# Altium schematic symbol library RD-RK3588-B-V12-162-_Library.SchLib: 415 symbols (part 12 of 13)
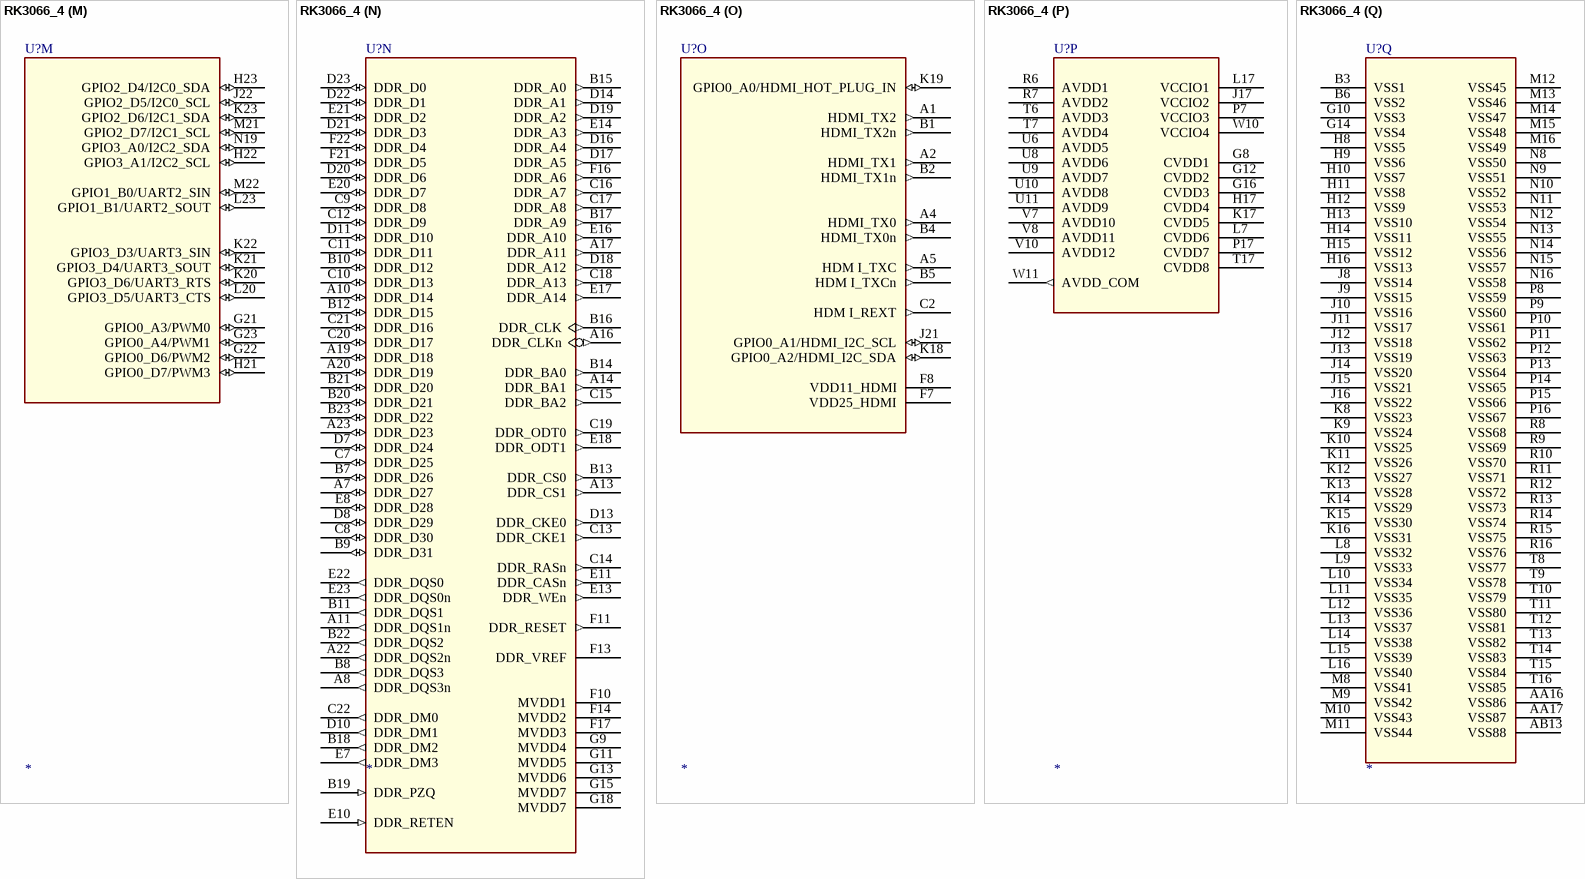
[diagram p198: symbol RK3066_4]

## RK3066_4
designator U?
footprint BGA453
part A pins: C3 LCD0_DEN (out), C4 LCD0_DCLK (out), C5 LCD0_VSYNC (out), C6 LCD0_HSYNC (out), D1 LCD0_D6 (out), D2 LCD0_D5 (out), D3 LCD0_D4 (out), D4 LCD0_D3 (out), D5 LCD0_D2 (out), D6 LCD0_D1 (out), E1 LCD0_D10 (out), E2 LCD0_D7 (out), E3 LCD0_D9 (out), E4 LCD0_D8 (out), E6 LCD0_D0 (out), F2 LCD0_D13 (out), F3 LCD0_D12 (out), F4 LCD0_D14 (out), F5 LCD0_D11 (out), G1 LCD0_D20 (out), G2 LCD0_D19 (out), G3 LCD0_D18 (out), G4 LCD0_D17 (out), G5 LCD0_D16 (out), G6 LCD0_D15 (out), H1 LCD0_D21 (out), H5 LCD0_D22 (out), H6 LCD0_D23 (out), H7 LCD0_VCC1 (power), J7 LCD0_VCC0 (power)
part B pins: H2 GPIO2_A0/LCD1_D0/SMC_A4 (io), H3 GPIO2_A1/LCD1_D1/SMC_A5 (io), H4 GPIO2_A2/LCD1_D2/SMC_A6 (io), J2 GPIO2_B7/LCD1_D14/SMC_A19/TS_D7 (io), J3 GPIO2_B6/LCD1_D14/SMC_A18/TS_SYNC (io), K1 GPIO2_C2/LCD1_D18/SMC_BIS_N1/TS_D5 (io), K2 GPIO2_C1/LCD1_D17/SMC_BIS_N0/TS_D6 (io), K3 GPIO2_B5/LCD1_D13/SMC_A17/TS_VALID (io), K4 GPIO2_C0/LCD1_D16/GPS_CLK/TS_CLKO (io), K7 LCD1_VCC (power), L1 GPIO2_C5/LCD1_D21/SPI1_RXD/TS_D2 (io), L2 GPIO2_C4/LCD1_D20/SPI1_CSN0/TS_D1 (io), L3 GPIO2_C3/LCD1_D19/SPI1_CLK/TS_D0 (io), L4 GPIO2_C7/LCD1_D23/SPI1_CSN1/TS_D4 (io), M2 GPIO2_C6/LCD1_D22/SPI1_RXD/TS_D3 (io)
part C pins: K5 CIF0_D5 (in), K6 CIF0_D2 (in), L5 CIF0_D9 (in), L6 CIF0_CLKIN (in), M3 CIF0_D8 (in), M7 CIF0_VCC (power), N1 CIF0_D4 (in), N2 CIF0_D3 (in), N3 CIF0_D7 (in), N4 GPIO1_B4/CIF0_D0 (io), N5 GPIO1_B3/CIF0_CLKO (io), N6 GPIO1_B5/CIF0_D1 (io), P1 CIF0_D6 (in), P2 CIF0_VSYNC (in), P3 CIF0_HREF (in), P4 GPIO1_B6/CIF0_D10 (io), P5 GPIO3_A3/I2C3_SCL (io), R2 GPIO3_A2/I2C3_SDA (io), R3 GPIO1_B7/CIF0_D11 (io)
part D pins: N7 CIF1_VCC (power), T1 GPIO1_C5/CIF1_D7/RMII_CRS_DVALID (io), T2 GPIO1_C0/CIF1_D2/RMII_CLKO (io), T3 GPIO1_C2/CIF1_D4/RMII_TXD1 (io), T4 GPIO1_C1/CIF1_D3/RMII_TX_EN (io), T5 GPIO1_C7/CIF1_D9/RMII_RXD0 (io), U1 GPIO1_D2/CIF1_CLKIN (io), U2 GPIO1_C4/CIF1_D6/RMII_RX_ERR (io), U3 GPIO1_C3/CIF1_D5/RMII_TXD0 (io), U4 GPIO1_D0/CIF1_VSYNC/MII_MD (io), U5 GPIO3_A5/I2C4_SCL (io), V2 GPIO1_D7/CIF1_CLKO (io), V3 GPIO1_C6/CIF1_D8/RMII_RXD1 (io), V4 GPIO1_D1/CIF1_HREF/MII_MDCLK (io), V5 GPIO3_A4/I2C4_SDA (io), W4 GPIO1_D6/CIF1_D11 (io)
part E pins: AA2 GPIO6_A4 (io), AA3 GPIO6_A5 (io), AA15 PVCC_3V3 (power), AB1 GPIO6_B0 (io), AB2 GPIO6_B1 (io), AB3 GPIO6_A1 (io), AB4 GPIO6_A7 (io), AB14 XOUT24M (out), AC1 GPIO6_A0 (io), AC2 GPIO6_A3 (io), AC4 GPIO6_A2 (io), AC5 GPIO6_A6 (io), AC13 DDRIO_RET_EN (out), AC14 XIN24M (in), U12 AVSS_APLL (power), U13 AVSS_DPLL (power), U14 AVSS_C/GPLL (power), V11 APLL_1V1 (power), V13 DPLL_1V1 (power), V14 C/GPLL_1V1 (power), V17 EFUSE (in), W13 PVDD_1V1 (power), Y1 CPU_PWROFF (out), Y2 CORE_PWROFF (out), Y3 DDRIO_PWROFF (out), Y4 GPIO6_B2 (io), Y5 GPIO6_B3 (io), Y13 CLKIN_32K (in), Y14 NPOR (in)
part F pins: AB15 HOST_RKELVIN (out), AB16 OTG_DM (io), AB17 HOST_DM (io), AC16 OTG_DP (io), AC17 HOST_DP (io), F19 GPIO0_A6/HOST_DRV (io), F20 TDO (out), G19 TDI/CPR_BYPASS (in), G20 TRSTN (in), H18 TCK/HSSCAN_SHIFT_CLOCK (in), H19 TMS/PLL_BYPASS (io), H20 RECOVER (in), P20 GPIO0_A5/OTG_DRV (io), U15 USBVDD_1V1 (power), U16 USBVDD_2V5 (power), V16 USBVDD_3V3 (power), W1 SARADC_ANI0 (in), W2 SARADC_ANI2 (in), W3 SARADC_ANI1 (in), W16 OTG_RKELVIN (out), W17 OTG_VBUS (in), Y17 OTG_ID (in)
part G pins: AA4 GPIO1_A4/UART1_RX/SPI0_CSN0 (io), AA5 GPIO4_B7/SPI0_CSN1 (io), AB5 GPIO1_A5/UART1_TX/SPI0_CLK (io), AB6 GPIO1_A6/UART1_CTSN/SPI0_RXD (io), AC7 GPIO1_A7/UART1_RTSN/SPI0_TXD (io), W18 AP1_VCC (power)
part H pins: AC23 GPIO3_B6/SDMMC0_DET (io), N22 GPIO3_B4/SDMMC0_D2 (io), N23 GPIO3_B5/SDMMC0_D3 (io), P18 GPIO3_A6/SDMMC0_RSTNO (io), P22 GPIO3_B3/SDMMC0_D1 (io), P23 GPIO3_B7/SDMMC0_WRITE_PRT (io), R22 GPIO3_A7/SDMMC0_PWR_EN (io), T21 GPIO3_B0/SDMMC0_CLKOUT (io), U19 GPIO3_B2/SDMMC0_D0 (io), U20 GPIO3_B1/SDMMC0_CMD (io)
part I pins: AA6 GPIO3_C1/SDMMC1_D0 (io), AA7 GPIO3_C2/SDMMC1_D1 (io), AA8 GPIO3_C7/SDMMC1_WRITE_PRT (io), AA9 GPIO1_A1/UART0_SOUT (io), AA10 GPIO0_C3/I2S1_LRCK_TX (io), AA12 GPIO1_A0/UART0_SIN (io), AB7 GPIO3_C0/SDMMC1_CMD (io), AB8 GPIO3_D2/SDMMC1_INT (io), AB9 GPIO0_C1/I2S1_SCLK (io), AB10 GPIO3_D1/SDMMC1_BACKEND (io), AB11 GPIO1_A2/UART0_CTS (io), AC8 GPIO3_C4/SDMMC1_D3 (io), AC10 GPIO3_C3/SDMMC1_D2 (io), AC11 GPIO0_C2/I2S1_LRCK_RX (io), U18 AP0_VCC (io), W6 GPIO3_C6/SDMMC1_DET (io), W7 GPIO0_C4/I2S1_SDI (io), W8 GPIO1_A3/UART0_RTS (io), Y6 GPIO3_C5/SDMMC1_CLKO (io), Y7 GPIO3_D0/SDMMC1_PWR_EN (io), Y8 GPIO0_C5/I2S1_SDO (io), Y11 GPIO0_C0/I2S1_CLK (io)
part J pins: AA11 GPIO4_C0/SMC_D0/TRACE_D0 (io), AA13 GPIO4_C4/SMC_D4/TRACE_D4 (io), AA14 GPIO4_D0/SMC_D8/TRACE_D8 (io), AA18 GPIO4_D3/SMC_D11/TRACE_D11 (io), AA19 GPIO4_D1/SMC_D9/TRACE_D9 (io), AA20 GPIO4_D5/SMC_D13/TRACE_D13 (io), AA21 GPIO0_D5/I2S2_SDO/SMC_A1 (io), AA22 GPIO0_D4/I2S2_SDI/SMC_A0 (io), AB12 GPIO4_C6/SMC_D6/TRACE_D6 (io), AB18 GPIO4_C3/SMC_D3/TRACE_D3 (io), AB19 GPIO4_D6/SMC_D14/TRACE_D14 (io), AB20 GPIO0_C7/SMC_A3/TRACE_CTL (io), AB21 GPIO0_D2/I2S2_LRCK_RX/SMC_OEN (io), AB23 GPIO0_C6/SMC_A2/TRACE_CLK (io), AC19 GPIO4_D7/SMC_D15/TRACE_D15 (io), AC20 GPIO4_D4/SMC_D12/TRACE_D12 (io), AC22 GPIO0_D3/I2S2_LRCK_TX/SMC_ADVN (io), R17 SMC_VCC (power), W14 GPIO4_C7/SMC_D7/TRACE_D7 (io), Y10 GPIO4_C1/SMC_D1/TRACE_D1 (io), Y16 GPIO4_C2/SMC_D2/TRACE_D2 (io), Y18 GPIO4_C5/SMC_D5/TRACE_D5 (io), Y19 GPIO4_D2/SMC_D10/TRACE_D10 (io), Y20 GPIO0_D1/I2S2_SCLK/SMC_WEN (io), Y23 GPIO0_D0/I2S2_CLK/SMC_CSN0 (io)
part K pins: AB22 FLASH_D0/EMMC_D0 (io), M17 FLASH_VCC0 (power), N17 FLASH_VCC1 (power), T18 GPIO4_B0/FLASH_CS1 (io), T19 GPIO4_B1/FLASH_CS2/EMMC_CMD (io), T20 GPIO4_B2/FLASH_CS3/EMMC_RST (io), T22 FLASH_ALE (out), T23 FLASH_CS0 (out), U21 FLASH_WP/EMMC_PWR_EN (out), U22 FLASH_D7/EMMC_D7 (io), U23 FLASH_D6/EMMC_D6 (io), V19 FLASH_RDN (out), V20 FLASH_CLE (out), V21 FLASH_RDY (out), V22 FLASH_D5/EMMC_D5 (io), W20 FLASH_WRN (out), W21 GPIO3_D7/FLASH_DQS/EMMC_CLKO (io), W22 FLASH_D4/EMMC_D4 (io), W23 FLASH_D3/EMMC_D3 (io), Y21 FLASH_D1/EMMC_D1 (io), Y22 FLASH_D2/EMMC_D2 (io)
part L pins: L18 GPIO0_B4/I2S0_D0 (io), L19 GPIO0_B7/I2S0_D3 (io), L21 GPIO1_B2/SPDIF_TX (io), L22 GPIO0_B5/I2S0_D1 (io), N18 GPIO0_B6/I2S0_D2 (io), N20 GPIO0_B2/I2S0_LRCK_RX (io), N21 GPIO0_B1/I2S0_SCLK (io), P19 GPIO0_A7/I2S0_SDI (io), P21 GPIO0_B3/I2S0_LRCK_TX (io), R21 GPIO0_B0/I2S0_CLK (io)
part M pins: G21 GPIO0_A3/PWM0 (io), G22 GPIO0_D6/PWM2 (io), G23 GPIO0_A4/PWM1 (io), H21 GPIO0_D7/PWM3 (io), H22 GPIO3_A1/I2C2_SCL (io), H23 GPIO2_D4/I2C0_SDA (io), J22 GPIO2_D5/I2C0_SCL (io), K20 GPIO3_D6/UART3_RTS (io), K21 GPIO3_D4/UART3_SOUT (io), K22 GPIO3_D3/UART3_SIN (io), K23 GPIO2_D6/I2C1_SDA (io), L20 GPIO3_D5/UART3_CTS (io), L23 GPIO1_B1/UART2_SOUT (io), M21 GPIO2_D7/I2C1_SCL (io), M22 GPIO1_B0/UART2_SIN (io), N19 GPIO3_A0/I2C2_SDA (io)
part N pins: A7 DDR_D27 (io), A8 DDR_DQS3n (out), A10 DDR_D14 (io), A11 DDR_DQS1n (out), A13 DDR_CS1 (out), A14 DDR_BA1 (out), A16 DDR_CLKn (out), A17 DDR_A11 (out), A19 DDR_D18 (io), A20 DDR_D19 (io), A22 DDR_DQS2n (out), A23 DDR_D23 (io), B7 DDR_D26 (io), B8 DDR_DQS3 (out), B9 DDR_D31 (io), B10 DDR_D12 (io), B11 DDR_DQS1 (out), B12 DDR_D15 (io), B13 DDR_CS0 (out), B14 DDR_BA0 (out), B15 DDR_A0 (out), B16 DDR_CLK (out), B17 DDR_A9 (out), B18 DDR_DM2 (out), B19 DDR_PZQ (in), B20 DDR_D21 (io), B21 DDR_D20 (io), B22 DDR_DQS2 (out), B23 DDR_D22 (io), C7 DDR_D25 (io), C8 DDR_D30 (io), C9 DDR_D8 (io), C10 DDR_D13 (io), C11 DDR_D11 (io), C12 DDR_D9 (io), C13 DDR_CKE1 (out), C14 DDR_RASn (out), C15 DDR_BA2 (out), C16 DDR_A7 (out), C17 DDR_A8 (out), C18 DDR_A13 (out), C19 DDR_ODT0 (out), C20 DDR_D17 (io), C21 DDR_D16 (io), C22 DDR_DM0 (out), D7 DDR_D24 (io), D8 DDR_D29 (io), D10 DDR_DM1 (out), D11 DDR_D10 (io), D13 DDR_CKE0 (out), D14 DDR_A1 (out), D16 DDR_A4 (out), D17 DDR_A5 (out), D18 DDR_A12 (out), D19 DDR_A2 (out), D20 DDR_D6 (io), D21 DDR_D3 (io), D22 DDR_D1 (io), D23 DDR_D0 (io), E7 DDR_DM3 (out), E8 DDR_D28 (io), E10 DDR_RETEN (in), E11 DDR_CASn (out), E13 DDR_WEn (out), E14 DDR_A3 (out), E16 DDR_A10 (out), E17 DDR_A14 (out), E18 DDR_ODT1 (out), E20 DDR_D7 (io), E21 DDR_D2 (io), E22 DDR_DQS0 (out), E23 DDR_DQS0n (out), F10 MVDD1 (power), F11 DDR_RESET (out), F13 DDR_VREF (power), F14 MVDD2 (power), F16 DDR_A6 (out), F17 MVDD3 (power), F21 DDR_D5 (io), F22 DDR_D4 (io), G9 MVDD4 (power), G11 MVDD5 (power), G13 MVDD6 (power), G15 MVDD7 (power), G18 MVDD7 (power)
part O pins: A1 HDMI_TX2 (out), A2 HDMI_TX1 (out), A4 HDMI_TX0 (out), A5 HDM I_TXC (out), B1 HDMI_TX2n (out), B2 HDMI_TX1n (out), B4 HDMI_TX0n (out), B5 HDM I_TXCn (out), C2 HDM I_REXT (out), F7 VDD25_HDMI (power), F8 VDD11_HDMI (power), J21 GPIO0_A1/HDMI_I2C_SCL (io), K18 GPIO0_A2/HDMI_I2C_SDA (io), K19 GPIO0_A0/HDMI_HOT_PLUG_IN (io)
part P pins: G8 CVDD1 (power), G12 CVDD2 (power), G16 CVDD3 (power), H17 CVDD4 (power), J17 VCCIO2 (power), K17 CVDD5 (power), L7 CVDD6 (power), L17 VCCIO1 (power), P7 VCCIO3 (power), P17 CVDD7 (power), R6 AVDD1 (power), R7 AVDD2 (power), T6 AVDD3 (power), T7 AVDD4 (power), T17 CVDD8 (power), U6 AVDD5 (power), U8 AVDD6 (power), U9 AVDD7 (power), U10 AVDD8 (power), U11 AVDD9 (power), V7 AVDD10 (power), V8 AVDD11 (power), V10 AVDD12 (power), W10 VCCIO4 (power), W11 AVDD_COM (out)
part Q pins: AA16 VSS86 (power), AA17 VSS87 (power), AB13 VSS88 (power), B3 VSS1 (power), B6 VSS2 (power), G10 VSS3 (power), G14 VSS4 (power), H8 VSS5 (power), H9 VSS6 (power), H10 VSS7 (power), H11 VSS8 (power), H12 VSS9 (power), H13 VSS10 (power), H14 VSS11 (power), H15 VSS12 (power), H16 VSS13 (power), J8 VSS14 (power), J9 VSS15 (power), J10 VSS16 (power), J11 VSS17 (power), J12 VSS18 (power), J13 VSS19 (power), J14 VSS20 (power), J15 VSS21 (power), J16 VSS22 (power), K8 VSS23 (power), K9 VSS24 (power), K10 VSS25 (power), K11 VSS26 (power), K12 VSS27 (power), K13 VSS28 (power), K14 VSS29 (power), K15 VSS30 (power), K16 VSS31 (power), L8 VSS32 (power), L9 VSS33 (power), L10 VSS34 (power), L11 VSS35 (power), L12 VSS36 (power), L13 VSS37 (power), L14 VSS38 (power), L15 VSS39 (power), L16 VSS40 (power), M8 VSS41 (power), M9 VSS42 (power), M10 VSS43 (power), M11 VSS44 (power), M12 VSS45 (power), M13 VSS46 (power), M14 VSS47 (power), M15 VSS48 (power), M16 VSS49 (power), N8 VSS50 (power), N9 VSS51 (power), N10 VSS52 (power), N11 VSS53 (power), N12 VSS54 (power), N13 VSS55 (power), N14 VSS56 (power), N15 VSS57 (power), N16 VSS58 (power), P8 VSS59 (power), P9 VSS60 (power), P10 VSS61 (power), P11 VSS62 (power), P12 VSS63 (power), P13 VSS64 (power), P14 VSS65 (power), P15 VSS66 (power), P16 VSS67 (power), R8 VSS68 (power), R9 VSS69 (power), R10 VSS70 (power), R11 VSS71 (power), R12 VSS72 (power), R13 VSS73 (power), R14 VSS74 (power), R15 VSS75 (power), R16 VSS76 (power), T8 VSS77 (power), T9 VSS78 (power), T10 VSS79 (power), T11 VSS80 (power), T12 VSS81 (power), T13 VSS82 (power), T14 VSS83 (power), T15 VSS84 (power), T16 VSS85 (power)

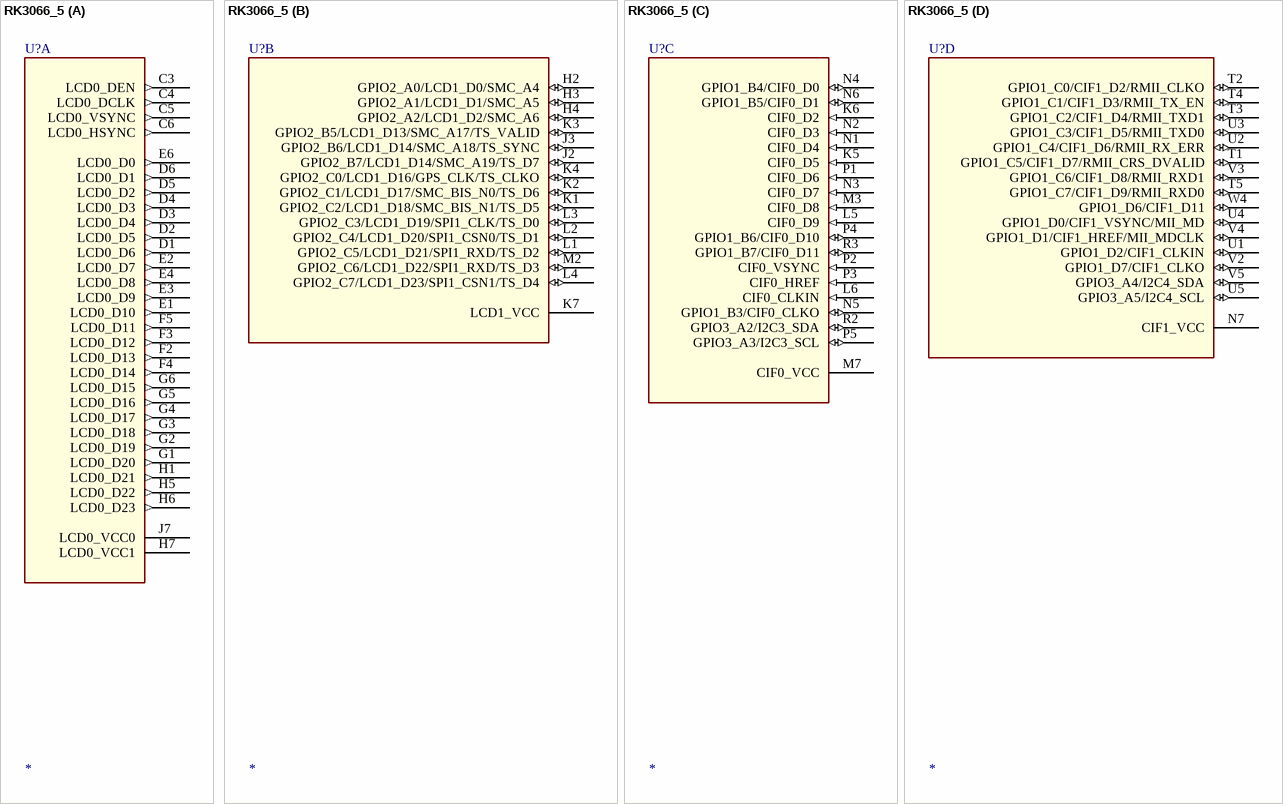
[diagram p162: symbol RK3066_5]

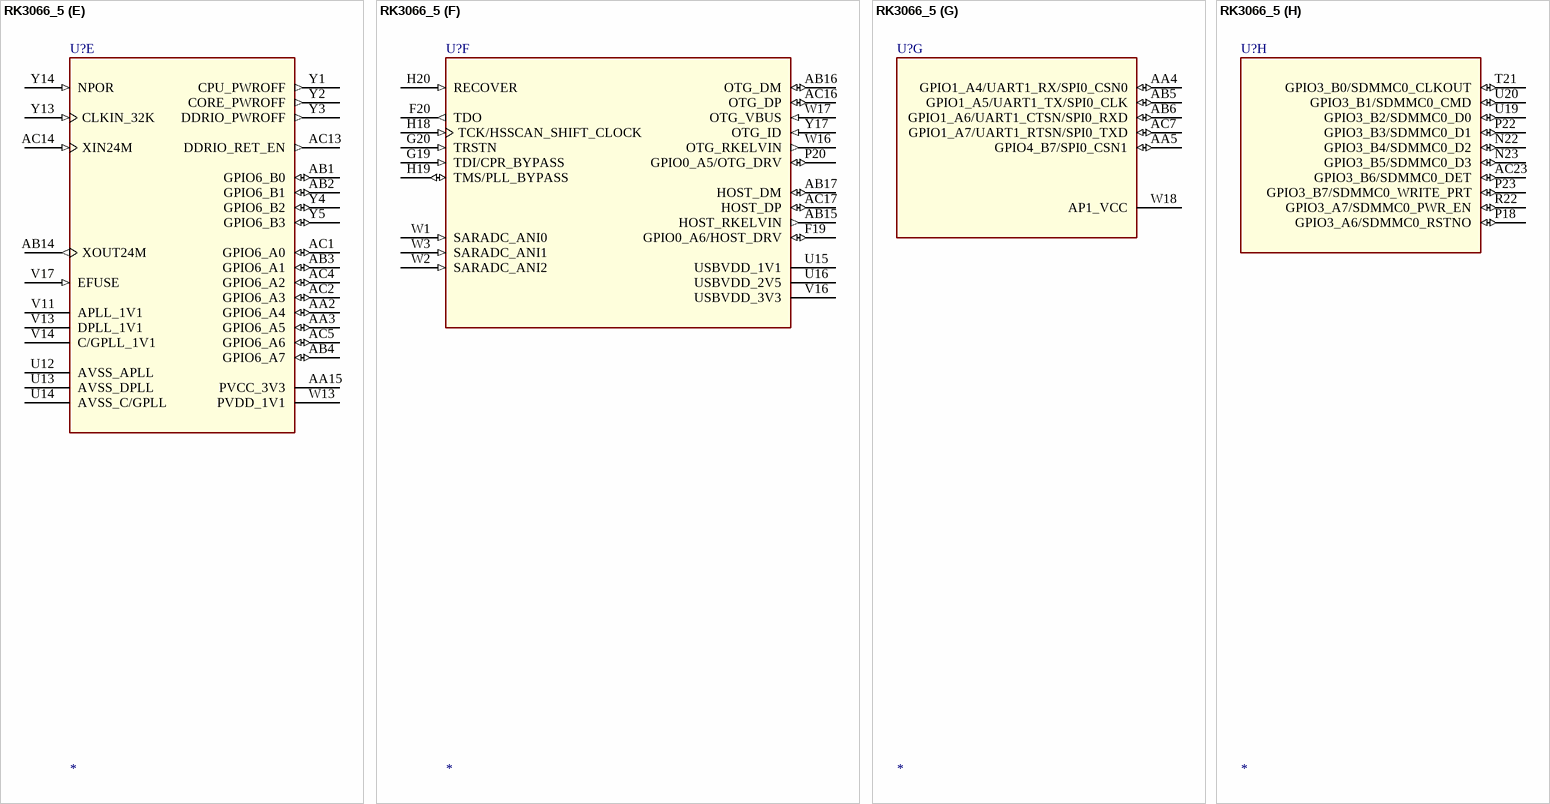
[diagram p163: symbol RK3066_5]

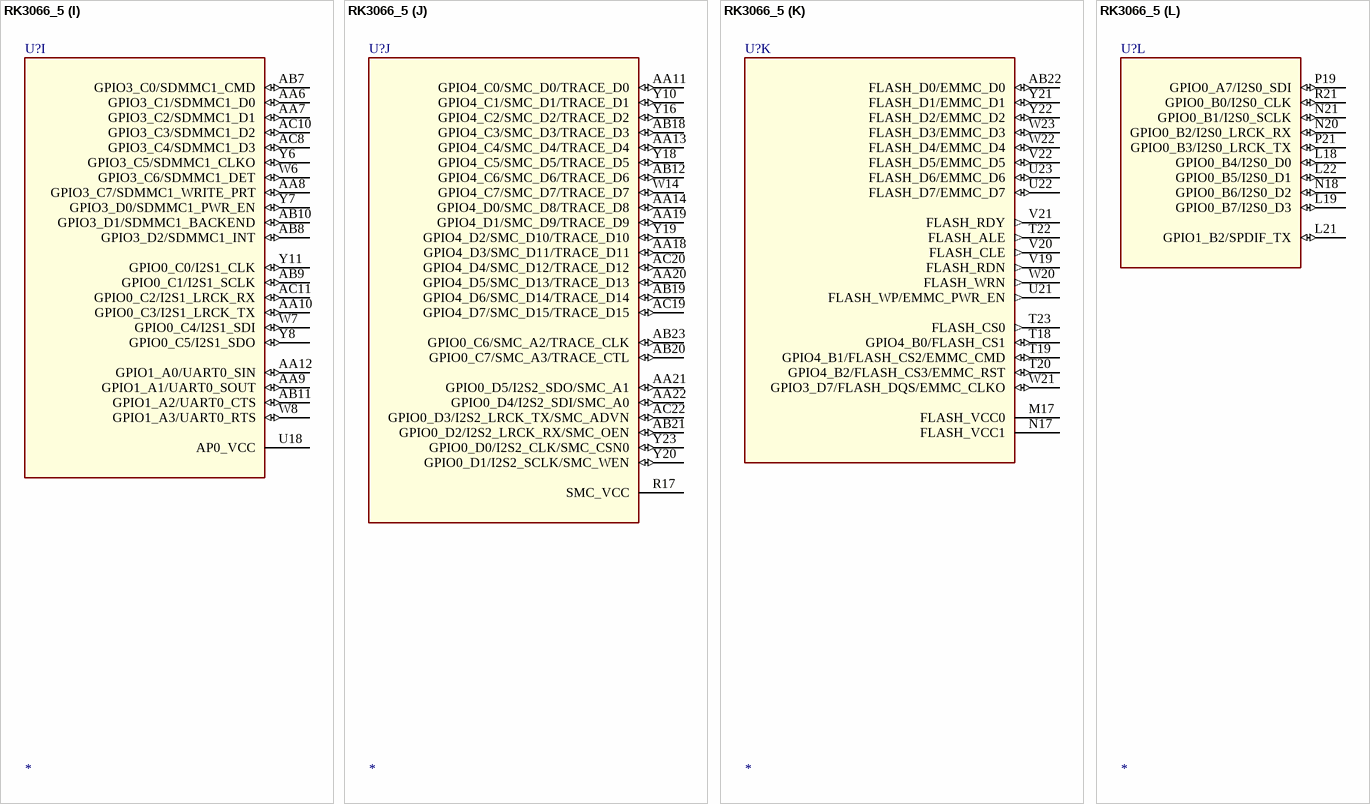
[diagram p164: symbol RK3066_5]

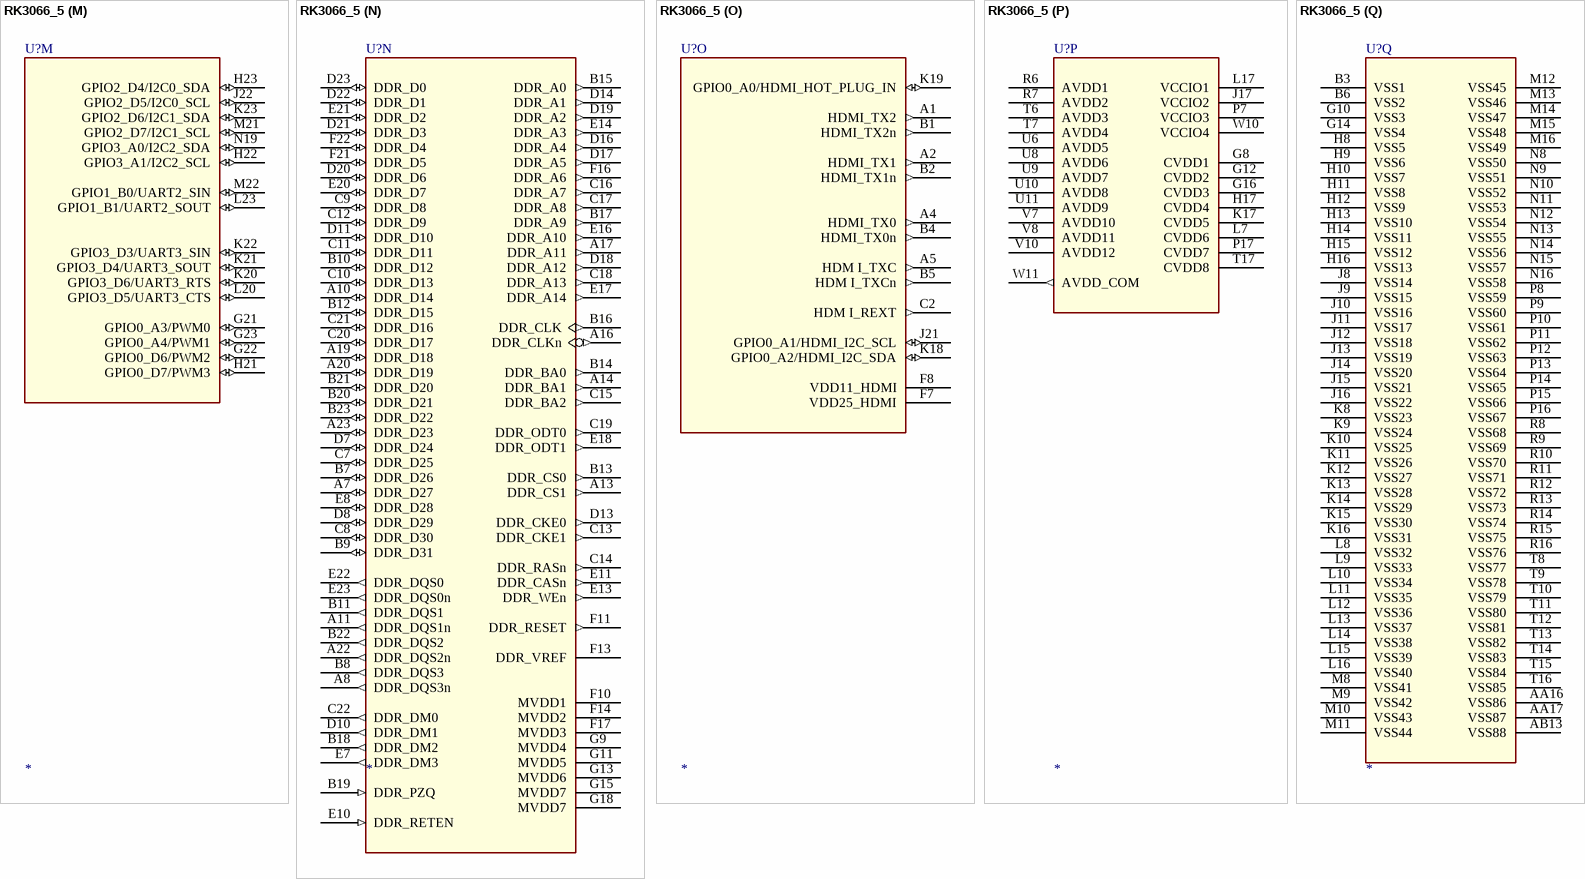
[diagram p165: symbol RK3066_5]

## RK3066_5
designator U?
footprint BGA453
part A pins: C3 LCD0_DEN (out), C4 LCD0_DCLK (out), C5 LCD0_VSYNC (out), C6 LCD0_HSYNC (out), D1 LCD0_D6 (out), D2 LCD0_D5 (out), D3 LCD0_D4 (out), D4 LCD0_D3 (out), D5 LCD0_D2 (out), D6 LCD0_D1 (out), E1 LCD0_D10 (out), E2 LCD0_D7 (out), E3 LCD0_D9 (out), E4 LCD0_D8 (out), E6 LCD0_D0 (out), F2 LCD0_D13 (out), F3 LCD0_D12 (out), F4 LCD0_D14 (out), F5 LCD0_D11 (out), G1 LCD0_D20 (out), G2 LCD0_D19 (out), G3 LCD0_D18 (out), G4 LCD0_D17 (out), G5 LCD0_D16 (out), G6 LCD0_D15 (out), H1 LCD0_D21 (out), H5 LCD0_D22 (out), H6 LCD0_D23 (out), H7 LCD0_VCC1 (power), J7 LCD0_VCC0 (power)
part B pins: H2 GPIO2_A0/LCD1_D0/SMC_A4 (io), H3 GPIO2_A1/LCD1_D1/SMC_A5 (io), H4 GPIO2_A2/LCD1_D2/SMC_A6 (io), J2 GPIO2_B7/LCD1_D14/SMC_A19/TS_D7 (io), J3 GPIO2_B6/LCD1_D14/SMC_A18/TS_SYNC (io), K1 GPIO2_C2/LCD1_D18/SMC_BIS_N1/TS_D5 (io), K2 GPIO2_C1/LCD1_D17/SMC_BIS_N0/TS_D6 (io), K3 GPIO2_B5/LCD1_D13/SMC_A17/TS_VALID (io), K4 GPIO2_C0/LCD1_D16/GPS_CLK/TS_CLKO (io), K7 LCD1_VCC (power), L1 GPIO2_C5/LCD1_D21/SPI1_RXD/TS_D2 (io), L2 GPIO2_C4/LCD1_D20/SPI1_CSN0/TS_D1 (io), L3 GPIO2_C3/LCD1_D19/SPI1_CLK/TS_D0 (io), L4 GPIO2_C7/LCD1_D23/SPI1_CSN1/TS_D4 (io), M2 GPIO2_C6/LCD1_D22/SPI1_RXD/TS_D3 (io)
part C pins: K5 CIF0_D5 (in), K6 CIF0_D2 (in), L5 CIF0_D9 (in), L6 CIF0_CLKIN (in), M3 CIF0_D8 (in), M7 CIF0_VCC (power), N1 CIF0_D4 (in), N2 CIF0_D3 (in), N3 CIF0_D7 (in), N4 GPIO1_B4/CIF0_D0 (io), N5 GPIO1_B3/CIF0_CLKO (io), N6 GPIO1_B5/CIF0_D1 (io), P1 CIF0_D6 (in), P2 CIF0_VSYNC (in), P3 CIF0_HREF (in), P4 GPIO1_B6/CIF0_D10 (io), P5 GPIO3_A3/I2C3_SCL (io), R2 GPIO3_A2/I2C3_SDA (io), R3 GPIO1_B7/CIF0_D11 (io)
part D pins: N7 CIF1_VCC (power), T1 GPIO1_C5/CIF1_D7/RMII_CRS_DVALID (io), T2 GPIO1_C0/CIF1_D2/RMII_CLKO (io), T3 GPIO1_C2/CIF1_D4/RMII_TXD1 (io), T4 GPIO1_C1/CIF1_D3/RMII_TX_EN (io), T5 GPIO1_C7/CIF1_D9/RMII_RXD0 (io), U1 GPIO1_D2/CIF1_CLKIN (io), U2 GPIO1_C4/CIF1_D6/RMII_RX_ERR (io), U3 GPIO1_C3/CIF1_D5/RMII_TXD0 (io), U4 GPIO1_D0/CIF1_VSYNC/MII_MD (io), U5 GPIO3_A5/I2C4_SCL (io), V2 GPIO1_D7/CIF1_CLKO (io), V3 GPIO1_C6/CIF1_D8/RMII_RXD1 (io), V4 GPIO1_D1/CIF1_HREF/MII_MDCLK (io), V5 GPIO3_A4/I2C4_SDA (io), W4 GPIO1_D6/CIF1_D11 (io)
part E pins: AA2 GPIO6_A4 (io), AA3 GPIO6_A5 (io), AA15 PVCC_3V3 (power), AB1 GPIO6_B0 (io), AB2 GPIO6_B1 (io), AB3 GPIO6_A1 (io), AB4 GPIO6_A7 (io), AB14 XOUT24M (out), AC1 GPIO6_A0 (io), AC2 GPIO6_A3 (io), AC4 GPIO6_A2 (io), AC5 GPIO6_A6 (io), AC13 DDRIO_RET_EN (out), AC14 XIN24M (in), U12 AVSS_APLL (power), U13 AVSS_DPLL (power), U14 AVSS_C/GPLL (power), V11 APLL_1V1 (power), V13 DPLL_1V1 (power), V14 C/GPLL_1V1 (power), V17 EFUSE (in), W13 PVDD_1V1 (power), Y1 CPU_PWROFF (out), Y2 CORE_PWROFF (out), Y3 DDRIO_PWROFF (out), Y4 GPIO6_B2 (io), Y5 GPIO6_B3 (io), Y13 CLKIN_32K (in), Y14 NPOR (in)
part F pins: AB15 HOST_RKELVIN (out), AB16 OTG_DM (io), AB17 HOST_DM (io), AC16 OTG_DP (io), AC17 HOST_DP (io), F19 GPIO0_A6/HOST_DRV (io), F20 TDO (out), G19 TDI/CPR_BYPASS (in), G20 TRSTN (in), H18 TCK/HSSCAN_SHIFT_CLOCK (in), H19 TMS/PLL_BYPASS (io), H20 RECOVER (in), P20 GPIO0_A5/OTG_DRV (io), U15 USBVDD_1V1 (power), U16 USBVDD_2V5 (power), V16 USBVDD_3V3 (power), W1 SARADC_ANI0 (in), W2 SARADC_ANI2 (in), W3 SARADC_ANI1 (in), W16 OTG_RKELVIN (out), W17 OTG_VBUS (in), Y17 OTG_ID (in)
part G pins: AA4 GPIO1_A4/UART1_RX/SPI0_CSN0 (io), AA5 GPIO4_B7/SPI0_CSN1 (io), AB5 GPIO1_A5/UART1_TX/SPI0_CLK (io), AB6 GPIO1_A6/UART1_CTSN/SPI0_RXD (io), AC7 GPIO1_A7/UART1_RTSN/SPI0_TXD (io), W18 AP1_VCC (power)
part H pins: AC23 GPIO3_B6/SDMMC0_DET (io), N22 GPIO3_B4/SDMMC0_D2 (io), N23 GPIO3_B5/SDMMC0_D3 (io), P18 GPIO3_A6/SDMMC0_RSTNO (io), P22 GPIO3_B3/SDMMC0_D1 (io), P23 GPIO3_B7/SDMMC0_WRITE_PRT (io), R22 GPIO3_A7/SDMMC0_PWR_EN (io), T21 GPIO3_B0/SDMMC0_CLKOUT (io), U19 GPIO3_B2/SDMMC0_D0 (io), U20 GPIO3_B1/SDMMC0_CMD (io)
part I pins: AA6 GPIO3_C1/SDMMC1_D0 (io), AA7 GPIO3_C2/SDMMC1_D1 (io), AA8 GPIO3_C7/SDMMC1_WRITE_PRT (io), AA9 GPIO1_A1/UART0_SOUT (io), AA10 GPIO0_C3/I2S1_LRCK_TX (io), AA12 GPIO1_A0/UART0_SIN (io), AB7 GPIO3_C0/SDMMC1_CMD (io), AB8 GPIO3_D2/SDMMC1_INT (io), AB9 GPIO0_C1/I2S1_SCLK (io), AB10 GPIO3_D1/SDMMC1_BACKEND (io), AB11 GPIO1_A2/UART0_CTS (io), AC8 GPIO3_C4/SDMMC1_D3 (io), AC10 GPIO3_C3/SDMMC1_D2 (io), AC11 GPIO0_C2/I2S1_LRCK_RX (io), U18 AP0_VCC (power), W6 GPIO3_C6/SDMMC1_DET (io), W7 GPIO0_C4/I2S1_SDI (io), W8 GPIO1_A3/UART0_RTS (io), Y6 GPIO3_C5/SDMMC1_CLKO (io), Y7 GPIO3_D0/SDMMC1_PWR_EN (io), Y8 GPIO0_C5/I2S1_SDO (io), Y11 GPIO0_C0/I2S1_CLK (io)
part J pins: AA11 GPIO4_C0/SMC_D0/TRACE_D0 (io), AA13 GPIO4_C4/SMC_D4/TRACE_D4 (io), AA14 GPIO4_D0/SMC_D8/TRACE_D8 (io), AA18 GPIO4_D3/SMC_D11/TRACE_D11 (io), AA19 GPIO4_D1/SMC_D9/TRACE_D9 (io), AA20 GPIO4_D5/SMC_D13/TRACE_D13 (io), AA21 GPIO0_D5/I2S2_SDO/SMC_A1 (io), AA22 GPIO0_D4/I2S2_SDI/SMC_A0 (io), AB12 GPIO4_C6/SMC_D6/TRACE_D6 (io), AB18 GPIO4_C3/SMC_D3/TRACE_D3 (io), AB19 GPIO4_D6/SMC_D14/TRACE_D14 (io), AB20 GPIO0_C7/SMC_A3/TRACE_CTL (io), AB21 GPIO0_D2/I2S2_LRCK_RX/SMC_OEN (io), AB23 GPIO0_C6/SMC_A2/TRACE_CLK (io), AC19 GPIO4_D7/SMC_D15/TRACE_D15 (io), AC20 GPIO4_D4/SMC_D12/TRACE_D12 (io), AC22 GPIO0_D3/I2S2_LRCK_TX/SMC_ADVN (io), R17 SMC_VCC (power), W14 GPIO4_C7/SMC_D7/TRACE_D7 (io), Y10 GPIO4_C1/SMC_D1/TRACE_D1 (io), Y16 GPIO4_C2/SMC_D2/TRACE_D2 (io), Y18 GPIO4_C5/SMC_D5/TRACE_D5 (io), Y19 GPIO4_D2/SMC_D10/TRACE_D10 (io), Y20 GPIO0_D1/I2S2_SCLK/SMC_WEN (io), Y23 GPIO0_D0/I2S2_CLK/SMC_CSN0 (io)
part K pins: AB22 FLASH_D0/EMMC_D0 (io), M17 FLASH_VCC0 (power), N17 FLASH_VCC1 (power), T18 GPIO4_B0/FLASH_CS1 (io), T19 GPIO4_B1/FLASH_CS2/EMMC_CMD (io), T20 GPIO4_B2/FLASH_CS3/EMMC_RST (io), T22 FLASH_ALE (out), T23 FLASH_CS0 (out), U21 FLASH_WP/EMMC_PWR_EN (out), U22 FLASH_D7/EMMC_D7 (io), U23 FLASH_D6/EMMC_D6 (io), V19 FLASH_RDN (out), V20 FLASH_CLE (out), V21 FLASH_RDY (out), V22 FLASH_D5/EMMC_D5 (io), W20 FLASH_WRN (out), W21 GPIO3_D7/FLASH_DQS/EMMC_CLKO (io), W22 FLASH_D4/EMMC_D4 (io), W23 FLASH_D3/EMMC_D3 (io), Y21 FLASH_D1/EMMC_D1 (io), Y22 FLASH_D2/EMMC_D2 (io)
part L pins: L18 GPIO0_B4/I2S0_D0 (io), L19 GPIO0_B7/I2S0_D3 (io), L21 GPIO1_B2/SPDIF_TX (io), L22 GPIO0_B5/I2S0_D1 (io), N18 GPIO0_B6/I2S0_D2 (io), N20 GPIO0_B2/I2S0_LRCK_RX (io), N21 GPIO0_B1/I2S0_SCLK (io), P19 GPIO0_A7/I2S0_SDI (io), P21 GPIO0_B3/I2S0_LRCK_TX (io), R21 GPIO0_B0/I2S0_CLK (io)
part M pins: G21 GPIO0_A3/PWM0 (io), G22 GPIO0_D6/PWM2 (io), G23 GPIO0_A4/PWM1 (io), H21 GPIO0_D7/PWM3 (io), H22 GPIO3_A1/I2C2_SCL (io), H23 GPIO2_D4/I2C0_SDA (io), J22 GPIO2_D5/I2C0_SCL (io), K20 GPIO3_D6/UART3_RTS (io), K21 GPIO3_D4/UART3_SOUT (io), K22 GPIO3_D3/UART3_SIN (io), K23 GPIO2_D6/I2C1_SDA (io), L20 GPIO3_D5/UART3_CTS (io), L23 GPIO1_B1/UART2_SOUT (io), M21 GPIO2_D7/I2C1_SCL (io), M22 GPIO1_B0/UART2_SIN (io), N19 GPIO3_A0/I2C2_SDA (io)
part N pins: A7 DDR_D27 (io), A8 DDR_DQS3n (out), A10 DDR_D14 (io), A11 DDR_DQS1n (out), A13 DDR_CS1 (out), A14 DDR_BA1 (out), A16 DDR_CLKn (out), A17 DDR_A11 (out), A19 DDR_D18 (io), A20 DDR_D19 (io), A22 DDR_DQS2n (out), A23 DDR_D23 (io), B7 DDR_D26 (io), B8 DDR_DQS3 (out), B9 DDR_D31 (io), B10 DDR_D12 (io), B11 DDR_DQS1 (out), B12 DDR_D15 (io), B13 DDR_CS0 (out), B14 DDR_BA0 (out), B15 DDR_A0 (out), B16 DDR_CLK (out), B17 DDR_A9 (out), B18 DDR_DM2 (out), B19 DDR_PZQ (in), B20 DDR_D21 (io), B21 DDR_D20 (io), B22 DDR_DQS2 (out), B23 DDR_D22 (io), C7 DDR_D25 (io), C8 DDR_D30 (io), C9 DDR_D8 (io), C10 DDR_D13 (io), C11 DDR_D11 (io), C12 DDR_D9 (io), C13 DDR_CKE1 (out), C14 DDR_RASn (out), C15 DDR_BA2 (out), C16 DDR_A7 (out), C17 DDR_A8 (out), C18 DDR_A13 (out), C19 DDR_ODT0 (out), C20 DDR_D17 (io), C21 DDR_D16 (io), C22 DDR_DM0 (out), D7 DDR_D24 (io), D8 DDR_D29 (io), D10 DDR_DM1 (out), D11 DDR_D10 (io), D13 DDR_CKE0 (out), D14 DDR_A1 (out), D16 DDR_A4 (out), D17 DDR_A5 (out), D18 DDR_A12 (out), D19 DDR_A2 (out), D20 DDR_D6 (io), D21 DDR_D3 (io), D22 DDR_D1 (io), D23 DDR_D0 (io), E7 DDR_DM3 (out), E8 DDR_D28 (io), E10 DDR_RETEN (in), E11 DDR_CASn (out), E13 DDR_WEn (out), E14 DDR_A3 (out), E16 DDR_A10 (out), E17 DDR_A14 (out), E18 DDR_ODT1 (out), E20 DDR_D7 (io), E21 DDR_D2 (io), E22 DDR_DQS0 (out), E23 DDR_DQS0n (out), F10 MVDD1 (power), F11 DDR_RESET (out), F13 DDR_VREF (power), F14 MVDD2 (power), F16 DDR_A6 (out), F17 MVDD3 (power), F21 DDR_D5 (io), F22 DDR_D4 (io), G9 MVDD4 (power), G11 MVDD5 (power), G13 MVDD6 (power), G15 MVDD7 (power), G18 MVDD7 (power)
part O pins: A1 HDMI_TX2 (out), A2 HDMI_TX1 (out), A4 HDMI_TX0 (out), A5 HDM I_TXC (out), B1 HDMI_TX2n (out), B2 HDMI_TX1n (out), B4 HDMI_TX0n (out), B5 HDM I_TXCn (out), C2 HDM I_REXT (out), F7 VDD25_HDMI (power), F8 VDD11_HDMI (power), J21 GPIO0_A1/HDMI_I2C_SCL (io), K18 GPIO0_A2/HDMI_I2C_SDA (io), K19 GPIO0_A0/HDMI_HOT_PLUG_IN (io)
part P pins: G8 CVDD1 (power), G12 CVDD2 (power), G16 CVDD3 (power), H17 CVDD4 (power), J17 VCCIO2 (power), K17 CVDD5 (power), L7 CVDD6 (power), L17 VCCIO1 (power), P7 VCCIO3 (power), P17 CVDD7 (power), R6 AVDD1 (power), R7 AVDD2 (power), T6 AVDD3 (power), T7 AVDD4 (power), T17 CVDD8 (power), U6 AVDD5 (power), U8 AVDD6 (power), U9 AVDD7 (power), U10 AVDD8 (power), U11 AVDD9 (power), V7 AVDD10 (power), V8 AVDD11 (power), V10 AVDD12 (power), W10 VCCIO4 (power), W11 AVDD_COM (out)
part Q pins: AA16 VSS86 (power), AA17 VSS87 (power), AB13 VSS88 (power), B3 VSS1 (power), B6 VSS2 (power), G10 VSS3 (power), G14 VSS4 (power), H8 VSS5 (power), H9 VSS6 (power), H10 VSS7 (power), H11 VSS8 (power), H12 VSS9 (power), H13 VSS10 (power), H14 VSS11 (power), H15 VSS12 (power), H16 VSS13 (power), J8 VSS14 (power), J9 VSS15 (power), J10 VSS16 (power), J11 VSS17 (power), J12 VSS18 (power), J13 VSS19 (power), J14 VSS20 (power), J15 VSS21 (power), J16 VSS22 (power), K8 VSS23 (power), K9 VSS24 (power), K10 VSS25 (power), K11 VSS26 (power), K12 VSS27 (power), K13 VSS28 (power), K14 VSS29 (power), K15 VSS30 (power), K16 VSS31 (power), L8 VSS32 (power), L9 VSS33 (power), L10 VSS34 (power), L11 VSS35 (power), L12 VSS36 (power), L13 VSS37 (power), L14 VSS38 (power), L15 VSS39 (power), L16 VSS40 (power), M8 VSS41 (power), M9 VSS42 (power), M10 VSS43 (power), M11 VSS44 (power), M12 VSS45 (power), M13 VSS46 (power), M14 VSS47 (power), M15 VSS48 (power), M16 VSS49 (power), N8 VSS50 (power), N9 VSS51 (power), N10 VSS52 (power), N11 VSS53 (power), N12 VSS54 (power), N13 VSS55 (power), N14 VSS56 (power), N15 VSS57 (power), N16 VSS58 (power), P8 VSS59 (power), P9 VSS60 (power), P10 VSS61 (power), P11 VSS62 (power), P12 VSS63 (power), P13 VSS64 (power), P14 VSS65 (power), P15 VSS66 (power), P16 VSS67 (power), R8 VSS68 (power), R9 VSS69 (power), R10 VSS70 (power), R11 VSS71 (power), R12 VSS72 (power), R13 VSS73 (power), R14 VSS74 (power), R15 VSS75 (power), R16 VSS76 (power), T8 VSS77 (power), T9 VSS78 (power), T10 VSS79 (power), T11 VSS80 (power), T12 VSS81 (power), T13 VSS82 (power), T14 VSS83 (power), T15 VSS84 (power), T16 VSS85 (power)

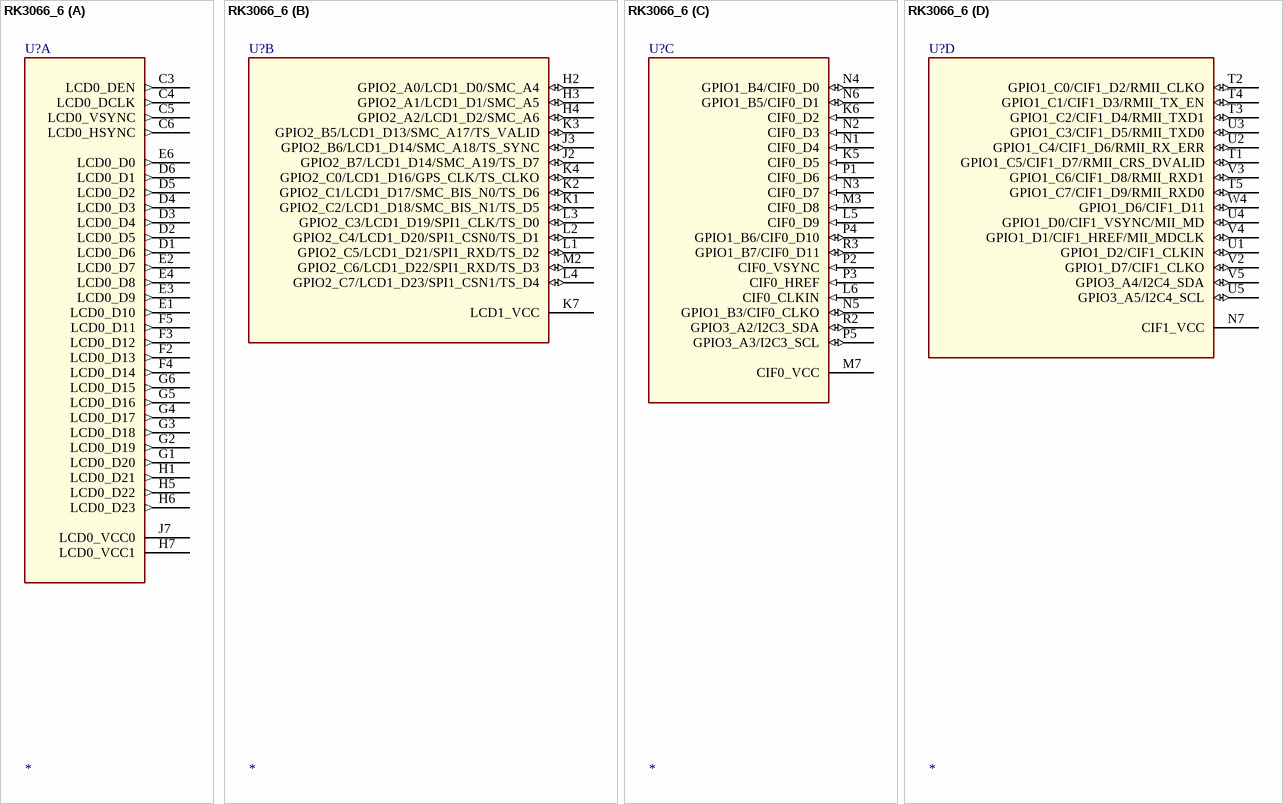
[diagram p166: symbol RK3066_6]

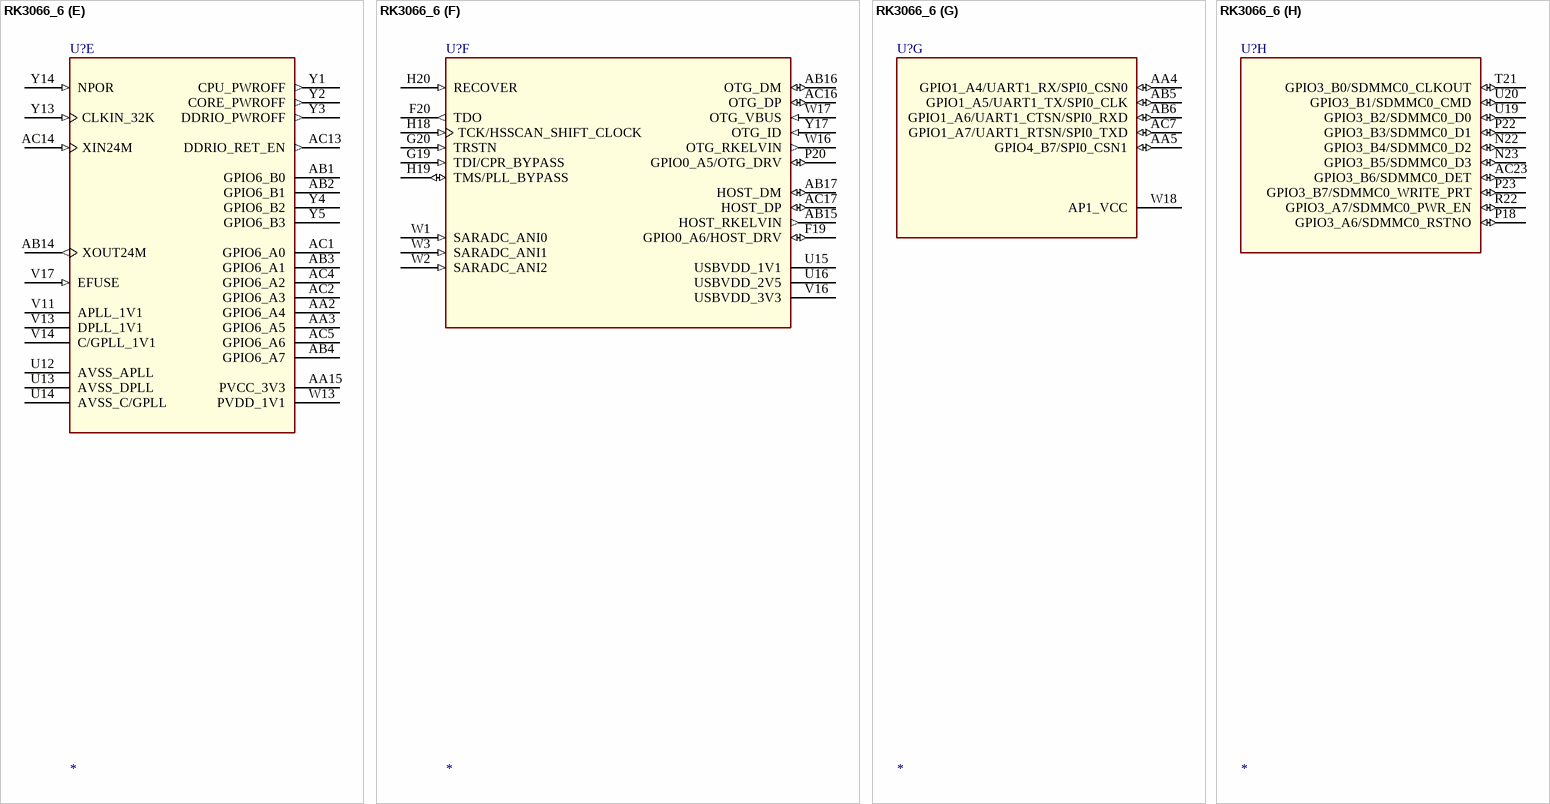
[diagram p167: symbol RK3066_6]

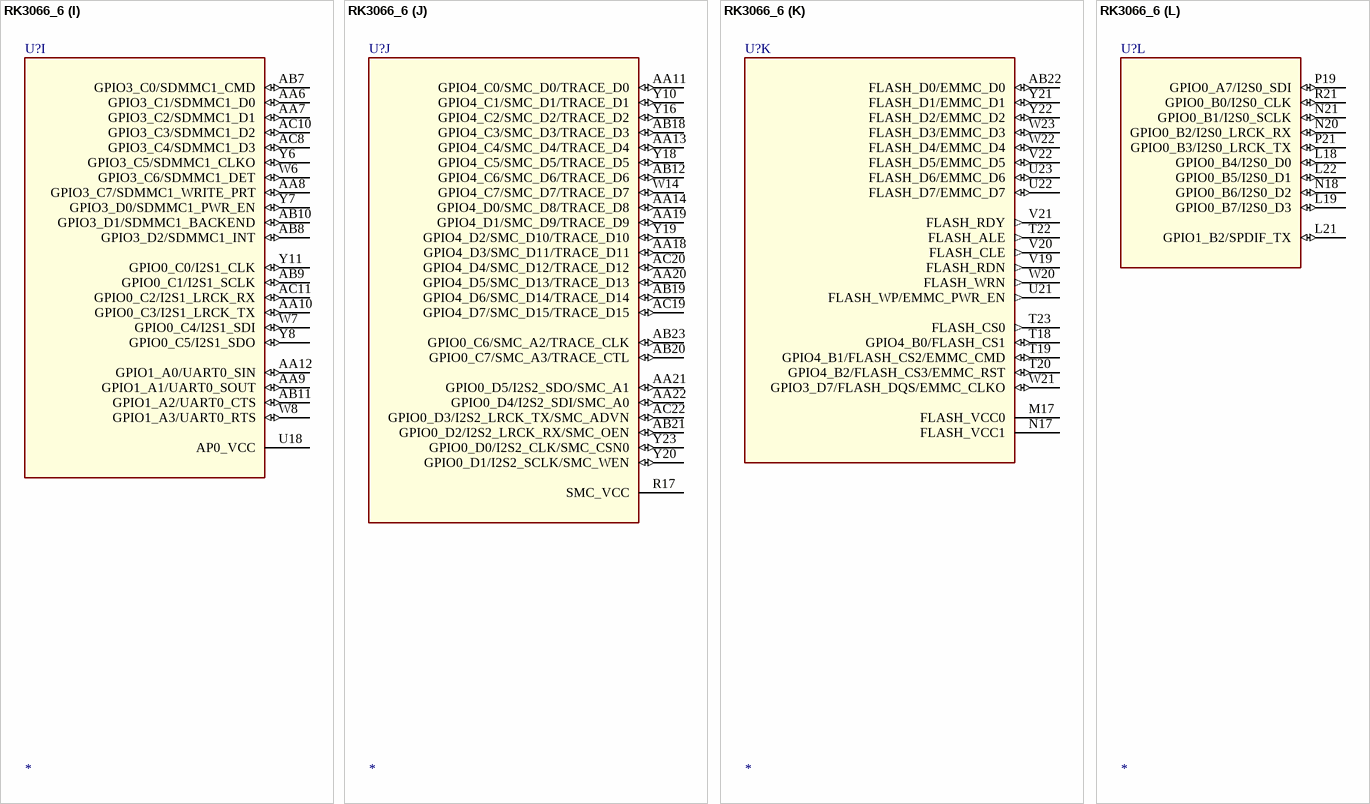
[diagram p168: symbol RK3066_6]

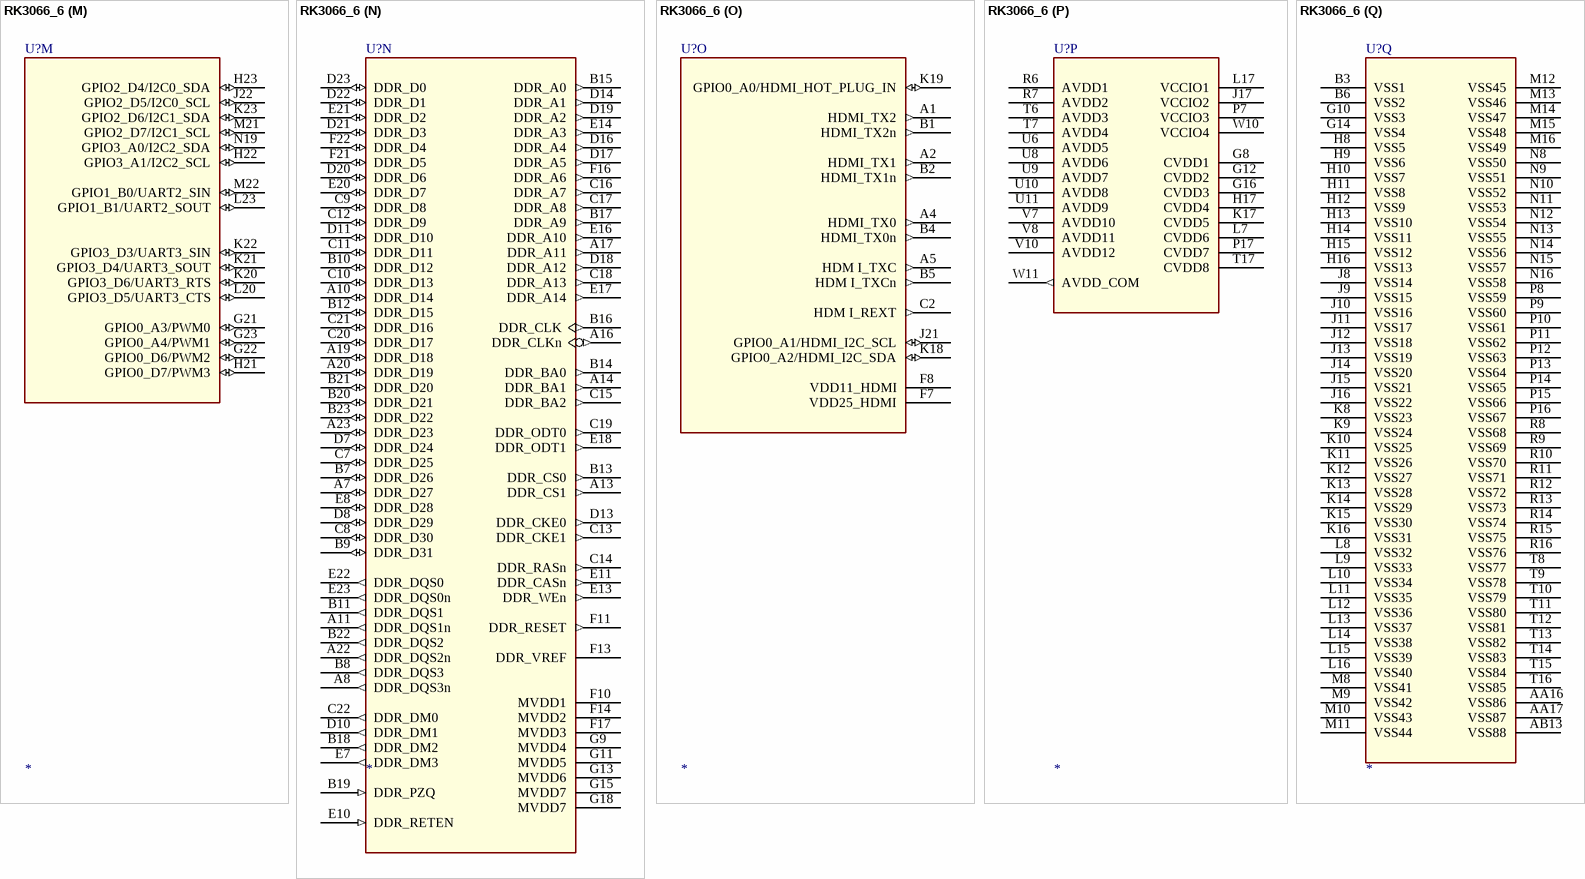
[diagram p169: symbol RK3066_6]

## RK3066_6
designator U?
footprint BGA453
part A pins: C3 LCD0_DEN (out), C4 LCD0_DCLK (out), C5 LCD0_VSYNC (out), C6 LCD0_HSYNC (out), D1 LCD0_D6 (out), D2 LCD0_D5 (out), D3 LCD0_D4 (out), D4 LCD0_D3 (out), D5 LCD0_D2 (out), D6 LCD0_D1 (out), E1 LCD0_D10 (out), E2 LCD0_D7 (out), E3 LCD0_D9 (out), E4 LCD0_D8 (out), E6 LCD0_D0 (out), F2 LCD0_D13 (out), F3 LCD0_D12 (out), F4 LCD0_D14 (out), F5 LCD0_D11 (out), G1 LCD0_D20 (out), G2 LCD0_D19 (out), G3 LCD0_D18 (out), G4 LCD0_D17 (out), G5 LCD0_D16 (out), G6 LCD0_D15 (out), H1 LCD0_D21 (out), H5 LCD0_D22 (out), H6 LCD0_D23 (out), H7 LCD0_VCC1 (power), J7 LCD0_VCC0 (power)
part B pins: H2 GPIO2_A0/LCD1_D0/SMC_A4 (io), H3 GPIO2_A1/LCD1_D1/SMC_A5 (io), H4 GPIO2_A2/LCD1_D2/SMC_A6 (io), J2 GPIO2_B7/LCD1_D14/SMC_A19/TS_D7 (io), J3 GPIO2_B6/LCD1_D14/SMC_A18/TS_SYNC (io), K1 GPIO2_C2/LCD1_D18/SMC_BIS_N1/TS_D5 (io), K2 GPIO2_C1/LCD1_D17/SMC_BIS_N0/TS_D6 (io), K3 GPIO2_B5/LCD1_D13/SMC_A17/TS_VALID (io), K4 GPIO2_C0/LCD1_D16/GPS_CLK/TS_CLKO (io), K7 LCD1_VCC (power), L1 GPIO2_C5/LCD1_D21/SPI1_RXD/TS_D2 (io), L2 GPIO2_C4/LCD1_D20/SPI1_CSN0/TS_D1 (io), L3 GPIO2_C3/LCD1_D19/SPI1_CLK/TS_D0 (io), L4 GPIO2_C7/LCD1_D23/SPI1_CSN1/TS_D4 (io), M2 GPIO2_C6/LCD1_D22/SPI1_RXD/TS_D3 (io)
part C pins: K5 CIF0_D5 (in), K6 CIF0_D2 (in), L5 CIF0_D9 (in), L6 CIF0_CLKIN (in), M3 CIF0_D8 (in), M7 CIF0_VCC (power), N1 CIF0_D4 (in), N2 CIF0_D3 (in), N3 CIF0_D7 (in), N4 GPIO1_B4/CIF0_D0 (io), N5 GPIO1_B3/CIF0_CLKO (io), N6 GPIO1_B5/CIF0_D1 (io), P1 CIF0_D6 (in), P2 CIF0_VSYNC (in), P3 CIF0_HREF (in), P4 GPIO1_B6/CIF0_D10 (io), P5 GPIO3_A3/I2C3_SCL (io), R2 GPIO3_A2/I2C3_SDA (io), R3 GPIO1_B7/CIF0_D11 (io)
part D pins: N7 CIF1_VCC (power), T1 GPIO1_C5/CIF1_D7/RMII_CRS_DVALID (io), T2 GPIO1_C0/CIF1_D2/RMII_CLKO (io), T3 GPIO1_C2/CIF1_D4/RMII_TXD1 (io), T4 GPIO1_C1/CIF1_D3/RMII_TX_EN (io), T5 GPIO1_C7/CIF1_D9/RMII_RXD0 (io), U1 GPIO1_D2/CIF1_CLKIN (io), U2 GPIO1_C4/CIF1_D6/RMII_RX_ERR (io), U3 GPIO1_C3/CIF1_D5/RMII_TXD0 (io), U4 GPIO1_D0/CIF1_VSYNC/MII_MD (io), U5 GPIO3_A5/I2C4_SCL (io), V2 GPIO1_D7/CIF1_CLKO (io), V3 GPIO1_C6/CIF1_D8/RMII_RXD1 (io), V4 GPIO1_D1/CIF1_HREF/MII_MDCLK (io), V5 GPIO3_A4/I2C4_SDA (io), W4 GPIO1_D6/CIF1_D11 (io)
part E pins: AA2 GPIO6_A4, AA3 GPIO6_A5, AA15 PVCC_3V3 (power), AB1 GPIO6_B0, AB2 GPIO6_B1, AB3 GPIO6_A1, AB4 GPIO6_A7, AB14 XOUT24M (out), AC1 GPIO6_A0, AC2 GPIO6_A3, AC4 GPIO6_A2, AC5 GPIO6_A6, AC13 DDRIO_RET_EN (out), AC14 XIN24M (in), U12 AVSS_APLL (power), U13 AVSS_DPLL (power), U14 AVSS_C/GPLL (power), V11 APLL_1V1 (power), V13 DPLL_1V1 (power), V14 C/GPLL_1V1 (power), V17 EFUSE (in), W13 PVDD_1V1 (power), Y1 CPU_PWROFF (out), Y2 CORE_PWROFF (out), Y3 DDRIO_PWROFF (out), Y4 GPIO6_B2, Y5 GPIO6_B3, Y13 CLKIN_32K (in), Y14 NPOR (in)
part F pins: AB15 HOST_RKELVIN (out), AB16 OTG_DM (io), AB17 HOST_DM (io), AC16 OTG_DP (io), AC17 HOST_DP (io), F19 GPIO0_A6/HOST_DRV (io), F20 TDO (out), G19 TDI/CPR_BYPASS (in), G20 TRSTN (in), H18 TCK/HSSCAN_SHIFT_CLOCK (in), H19 TMS/PLL_BYPASS (io), H20 RECOVER (in), P20 GPIO0_A5/OTG_DRV (io), U15 USBVDD_1V1 (power), U16 USBVDD_2V5 (power), V16 USBVDD_3V3 (power), W1 SARADC_ANI0 (in), W2 SARADC_ANI2 (in), W3 SARADC_ANI1 (in), W16 OTG_RKELVIN (out), W17 OTG_VBUS (in), Y17 OTG_ID (in)
part G pins: AA4 GPIO1_A4/UART1_RX/SPI0_CSN0 (io), AA5 GPIO4_B7/SPI0_CSN1 (io), AB5 GPIO1_A5/UART1_TX/SPI0_CLK (io), AB6 GPIO1_A6/UART1_CTSN/SPI0_RXD (io), AC7 GPIO1_A7/UART1_RTSN/SPI0_TXD (io), W18 AP1_VCC (power)
part H pins: AC23 GPIO3_B6/SDMMC0_DET (io), N22 GPIO3_B4/SDMMC0_D2 (io), N23 GPIO3_B5/SDMMC0_D3 (io), P18 GPIO3_A6/SDMMC0_RSTNO (io), P22 GPIO3_B3/SDMMC0_D1 (io), P23 GPIO3_B7/SDMMC0_WRITE_PRT (io), R22 GPIO3_A7/SDMMC0_PWR_EN (io), T21 GPIO3_B0/SDMMC0_CLKOUT (io), U19 GPIO3_B2/SDMMC0_D0 (io), U20 GPIO3_B1/SDMMC0_CMD (io)
part I pins: AA6 GPIO3_C1/SDMMC1_D0 (io), AA7 GPIO3_C2/SDMMC1_D1 (io), AA8 GPIO3_C7/SDMMC1_WRITE_PRT (io), AA9 GPIO1_A1/UART0_SOUT (io), AA10 GPIO0_C3/I2S1_LRCK_TX (io), AA12 GPIO1_A0/UART0_SIN (io), AB7 GPIO3_C0/SDMMC1_CMD (io), AB8 GPIO3_D2/SDMMC1_INT (io), AB9 GPIO0_C1/I2S1_SCLK (io), AB10 GPIO3_D1/SDMMC1_BACKEND (io), AB11 GPIO1_A2/UART0_CTS (io), AC8 GPIO3_C4/SDMMC1_D3 (io), AC10 GPIO3_C3/SDMMC1_D2 (io), AC11 GPIO0_C2/I2S1_LRCK_RX (io), U18 AP0_VCC (power), W6 GPIO3_C6/SDMMC1_DET (io), W7 GPIO0_C4/I2S1_SDI (io), W8 GPIO1_A3/UART0_RTS (io), Y6 GPIO3_C5/SDMMC1_CLKO (io), Y7 GPIO3_D0/SDMMC1_PWR_EN (io), Y8 GPIO0_C5/I2S1_SDO (io), Y11 GPIO0_C0/I2S1_CLK (io)
part J pins: AA11 GPIO4_C0/SMC_D0/TRACE_D0 (io), AA13 GPIO4_C4/SMC_D4/TRACE_D4 (io), AA14 GPIO4_D0/SMC_D8/TRACE_D8 (io), AA18 GPIO4_D3/SMC_D11/TRACE_D11 (io), AA19 GPIO4_D1/SMC_D9/TRACE_D9 (io), AA20 GPIO4_D5/SMC_D13/TRACE_D13 (io), AA21 GPIO0_D5/I2S2_SDO/SMC_A1 (io), AA22 GPIO0_D4/I2S2_SDI/SMC_A0 (io), AB12 GPIO4_C6/SMC_D6/TRACE_D6 (io), AB18 GPIO4_C3/SMC_D3/TRACE_D3 (io), AB19 GPIO4_D6/SMC_D14/TRACE_D14 (io), AB20 GPIO0_C7/SMC_A3/TRACE_CTL (io), AB21 GPIO0_D2/I2S2_LRCK_RX/SMC_OEN (io), AB23 GPIO0_C6/SMC_A2/TRACE_CLK (io), AC19 GPIO4_D7/SMC_D15/TRACE_D15 (io), AC20 GPIO4_D4/SMC_D12/TRACE_D12 (io), AC22 GPIO0_D3/I2S2_LRCK_TX/SMC_ADVN (io), R17 SMC_VCC (power), W14 GPIO4_C7/SMC_D7/TRACE_D7 (io), Y10 GPIO4_C1/SMC_D1/TRACE_D1 (io), Y16 GPIO4_C2/SMC_D2/TRACE_D2 (io), Y18 GPIO4_C5/SMC_D5/TRACE_D5 (io), Y19 GPIO4_D2/SMC_D10/TRACE_D10 (io), Y20 GPIO0_D1/I2S2_SCLK/SMC_WEN (io), Y23 GPIO0_D0/I2S2_CLK/SMC_CSN0 (io)
part K pins: AB22 FLASH_D0/EMMC_D0 (io), M17 FLASH_VCC0 (power), N17 FLASH_VCC1 (power), T18 GPIO4_B0/FLASH_CS1 (io), T19 GPIO4_B1/FLASH_CS2/EMMC_CMD (io), T20 GPIO4_B2/FLASH_CS3/EMMC_RST (io), T22 FLASH_ALE (out), T23 FLASH_CS0 (out), U21 FLASH_WP/EMMC_PWR_EN (out), U22 FLASH_D7/EMMC_D7 (io), U23 FLASH_D6/EMMC_D6 (io), V19 FLASH_RDN (out), V20 FLASH_CLE (out), V21 FLASH_RDY (out), V22 FLASH_D5/EMMC_D5 (io), W20 FLASH_WRN (out), W21 GPIO3_D7/FLASH_DQS/EMMC_CLKO (io), W22 FLASH_D4/EMMC_D4 (io), W23 FLASH_D3/EMMC_D3 (io), Y21 FLASH_D1/EMMC_D1 (io), Y22 FLASH_D2/EMMC_D2 (io)
part L pins: L18 GPIO0_B4/I2S0_D0 (io), L19 GPIO0_B7/I2S0_D3 (io), L21 GPIO1_B2/SPDIF_TX (io), L22 GPIO0_B5/I2S0_D1 (io), N18 GPIO0_B6/I2S0_D2 (io), N20 GPIO0_B2/I2S0_LRCK_RX (io), N21 GPIO0_B1/I2S0_SCLK (io), P19 GPIO0_A7/I2S0_SDI (io), P21 GPIO0_B3/I2S0_LRCK_TX (io), R21 GPIO0_B0/I2S0_CLK (io)
part M pins: G21 GPIO0_A3/PWM0 (io), G22 GPIO0_D6/PWM2 (io), G23 GPIO0_A4/PWM1 (io), H21 GPIO0_D7/PWM3 (io), H22 GPIO3_A1/I2C2_SCL (io), H23 GPIO2_D4/I2C0_SDA (io), J22 GPIO2_D5/I2C0_SCL (io), K20 GPIO3_D6/UART3_RTS (io), K21 GPIO3_D4/UART3_SOUT (io), K22 GPIO3_D3/UART3_SIN (io), K23 GPIO2_D6/I2C1_SDA (io), L20 GPIO3_D5/UART3_CTS (io), L23 GPIO1_B1/UART2_SOUT (io), M21 GPIO2_D7/I2C1_SCL (io), M22 GPIO1_B0/UART2_SIN (io), N19 GPIO3_A0/I2C2_SDA (io)
part N pins: A7 DDR_D27 (io), A8 DDR_DQS3n (out), A10 DDR_D14 (io), A11 DDR_DQS1n (out), A13 DDR_CS1 (out), A14 DDR_BA1 (out), A16 DDR_CLKn (out), A17 DDR_A11 (out), A19 DDR_D18 (io), A20 DDR_D19 (io), A22 DDR_DQS2n (out), A23 DDR_D23 (io), B7 DDR_D26 (io), B8 DDR_DQS3 (out), B9 DDR_D31 (io), B10 DDR_D12 (io), B11 DDR_DQS1 (out), B12 DDR_D15 (io), B13 DDR_CS0 (out), B14 DDR_BA0 (out), B15 DDR_A0 (out), B16 DDR_CLK (out), B17 DDR_A9 (out), B18 DDR_DM2 (out), B19 DDR_PZQ (in), B20 DDR_D21 (io), B21 DDR_D20 (io), B22 DDR_DQS2 (out), B23 DDR_D22 (io), C7 DDR_D25 (io), C8 DDR_D30 (io), C9 DDR_D8 (io), C10 DDR_D13 (io), C11 DDR_D11 (io), C12 DDR_D9 (io), C13 DDR_CKE1 (out), C14 DDR_RASn (out), C15 DDR_BA2 (out), C16 DDR_A7 (out), C17 DDR_A8 (out), C18 DDR_A13 (out), C19 DDR_ODT0 (out), C20 DDR_D17 (io), C21 DDR_D16 (io), C22 DDR_DM0 (out), D7 DDR_D24 (io), D8 DDR_D29 (io), D10 DDR_DM1 (out), D11 DDR_D10 (io), D13 DDR_CKE0 (out), D14 DDR_A1 (out), D16 DDR_A4 (out), D17 DDR_A5 (out), D18 DDR_A12 (out), D19 DDR_A2 (out), D20 DDR_D6 (io), D21 DDR_D3 (io), D22 DDR_D1 (io), D23 DDR_D0 (io), E7 DDR_DM3 (out), E8 DDR_D28 (io), E10 DDR_RETEN (in), E11 DDR_CASn (out), E13 DDR_WEn (out), E14 DDR_A3 (out), E16 DDR_A10 (out), E17 DDR_A14 (out), E18 DDR_ODT1 (out), E20 DDR_D7 (io), E21 DDR_D2 (io), E22 DDR_DQS0 (out), E23 DDR_DQS0n (out), F10 MVDD1 (power), F11 DDR_RESET (out), F13 DDR_VREF (power), F14 MVDD2 (power), F16 DDR_A6 (out), F17 MVDD3 (power), F21 DDR_D5 (io), F22 DDR_D4 (io), G9 MVDD4 (power), G11 MVDD5 (power), G13 MVDD6 (power), G15 MVDD7 (power), G18 MVDD7 (power)
part O pins: A1 HDMI_TX2 (out), A2 HDMI_TX1 (out), A4 HDMI_TX0 (out), A5 HDM I_TXC (out), B1 HDMI_TX2n (out), B2 HDMI_TX1n (out), B4 HDMI_TX0n (out), B5 HDM I_TXCn (out), C2 HDM I_REXT (out), F7 VDD25_HDMI (power), F8 VDD11_HDMI (power), J21 GPIO0_A1/HDMI_I2C_SCL (io), K18 GPIO0_A2/HDMI_I2C_SDA (io), K19 GPIO0_A0/HDMI_HOT_PLUG_IN (io)
part P pins: G8 CVDD1 (power), G12 CVDD2 (power), G16 CVDD3 (power), H17 CVDD4 (power), J17 VCCIO2 (power), K17 CVDD5 (power), L7 CVDD6 (power), L17 VCCIO1 (power), P7 VCCIO3 (power), P17 CVDD7 (power), R6 AVDD1 (power), R7 AVDD2 (power), T6 AVDD3 (power), T7 AVDD4 (power), T17 CVDD8 (power), U6 AVDD5 (power), U8 AVDD6 (power), U9 AVDD7 (power), U10 AVDD8 (power), U11 AVDD9 (power), V7 AVDD10 (power), V8 AVDD11 (power), V10 AVDD12 (power), W10 VCCIO4 (power), W11 AVDD_COM (out)
part Q pins: AA16 VSS86 (power), AA17 VSS87 (power), AB13 VSS88 (power), B3 VSS1 (power), B6 VSS2 (power), G10 VSS3 (power), G14 VSS4 (power), H8 VSS5 (power), H9 VSS6 (power), H10 VSS7 (power), H11 VSS8 (power), H12 VSS9 (power), H13 VSS10 (power), H14 VSS11 (power), H15 VSS12 (power), H16 VSS13 (power), J8 VSS14 (power), J9 VSS15 (power), J10 VSS16 (power), J11 VSS17 (power), J12 VSS18 (power), J13 VSS19 (power), J14 VSS20 (power), J15 VSS21 (power), J16 VSS22 (power), K8 VSS23 (power), K9 VSS24 (power), K10 VSS25 (power), K11 VSS26 (power), K12 VSS27 (power), K13 VSS28 (power), K14 VSS29 (power), K15 VSS30 (power), K16 VSS31 (power), L8 VSS32 (power), L9 VSS33 (power), L10 VSS34 (power), L11 VSS35 (power), L12 VSS36 (power), L13 VSS37 (power), L14 VSS38 (power), L15 VSS39 (power), L16 VSS40 (power), M8 VSS41 (power), M9 VSS42 (power), M10 VSS43 (power), M11 VSS44 (power), M12 VSS45 (power), M13 VSS46 (power), M14 VSS47 (power), M15 VSS48 (power), M16 VSS49 (power), N8 VSS50 (power), N9 VSS51 (power), N10 VSS52 (power), N11 VSS53 (power), N12 VSS54 (power), N13 VSS55 (power), N14 VSS56 (power), N15 VSS57 (power), N16 VSS58 (power), P8 VSS59 (power), P9 VSS60 (power), P10 VSS61 (power), P11 VSS62 (power), P12 VSS63 (power), P13 VSS64 (power), P14 VSS65 (power), P15 VSS66 (power), P16 VSS67 (power), R8 VSS68 (power), R9 VSS69 (power), R10 VSS70 (power), R11 VSS71 (power), R12 VSS72 (power), R13 VSS73 (power), R14 VSS74 (power), R15 VSS75 (power), R16 VSS76 (power), T8 VSS77 (power), T9 VSS78 (power), T10 VSS79 (power), T11 VSS80 (power), T12 VSS81 (power), T13 VSS82 (power), T14 VSS83 (power), T15 VSS84 (power), T16 VSS85 (power)

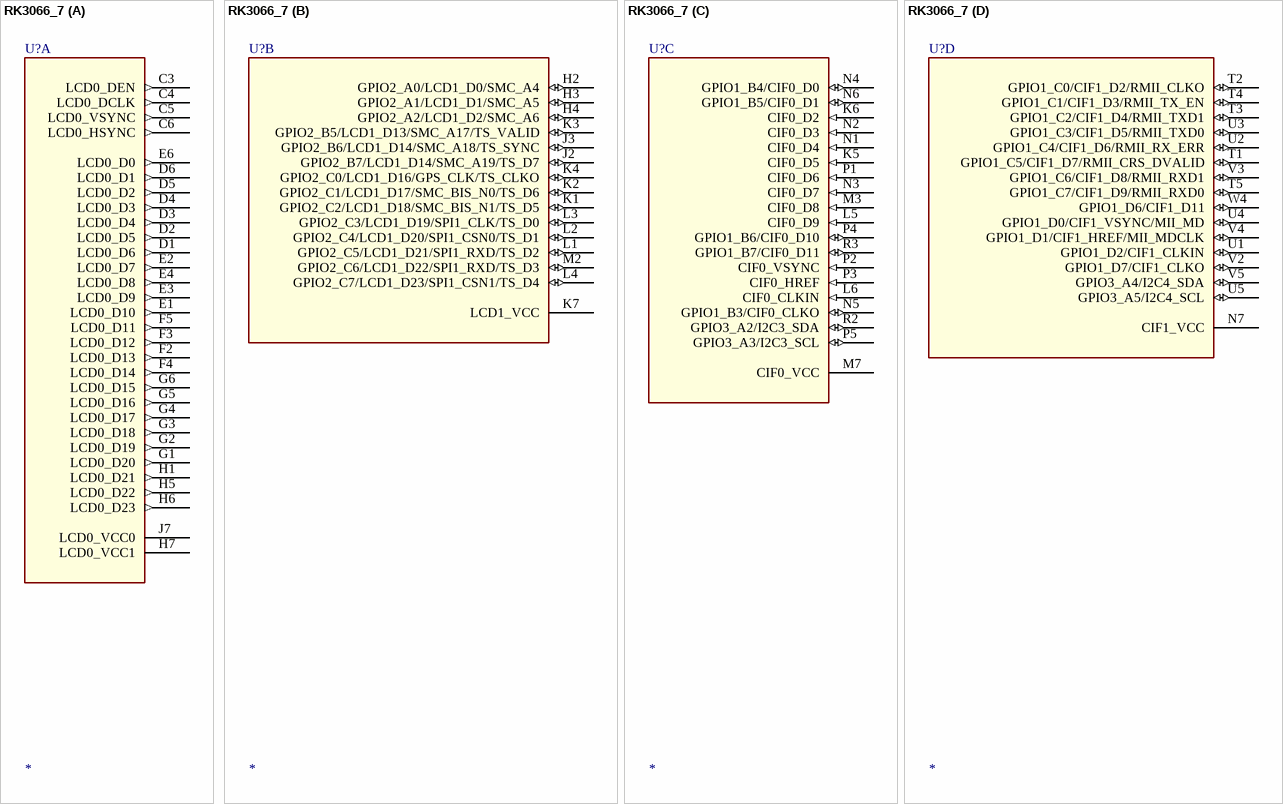
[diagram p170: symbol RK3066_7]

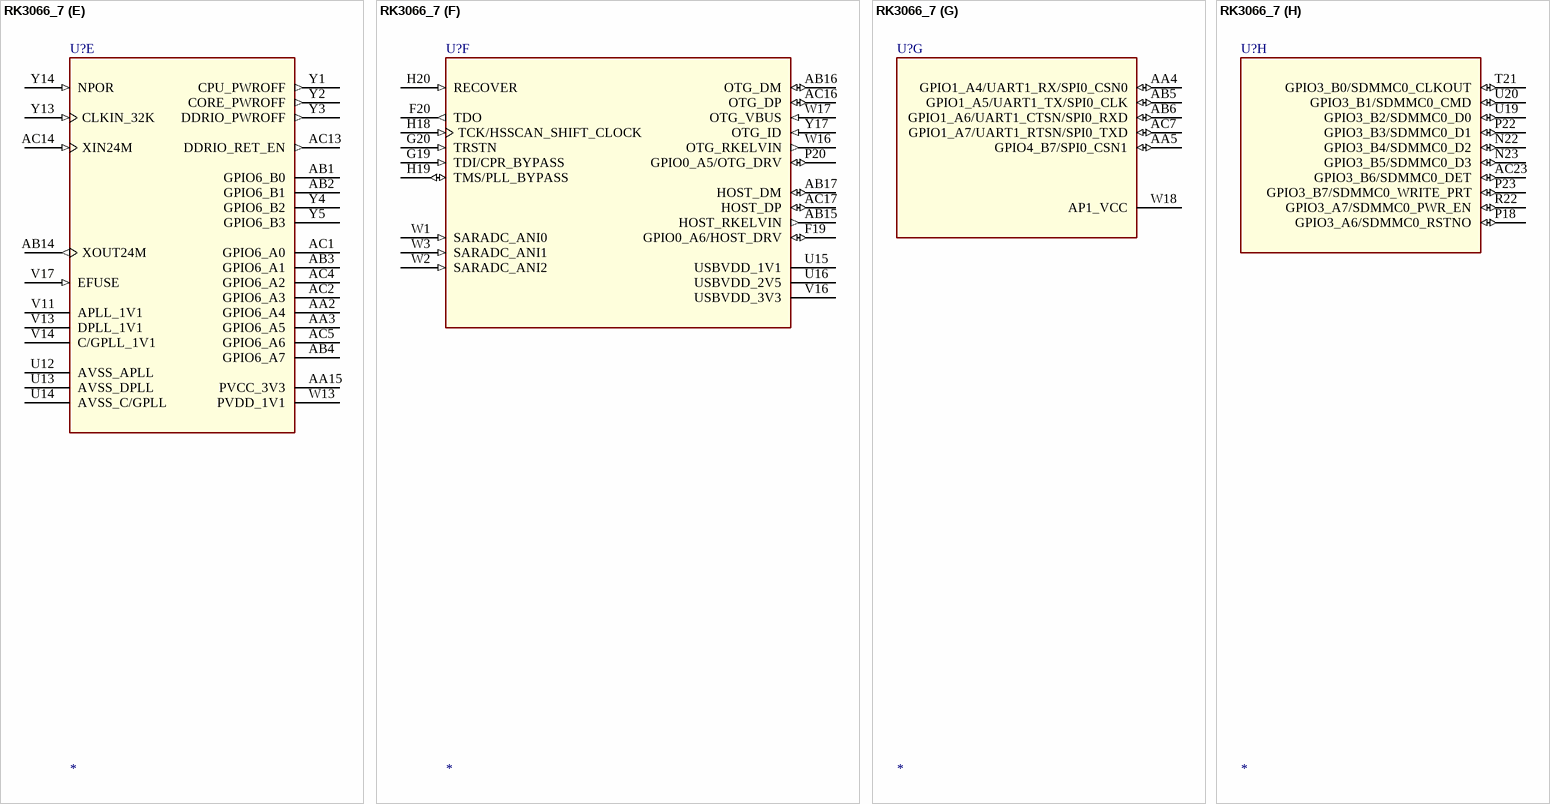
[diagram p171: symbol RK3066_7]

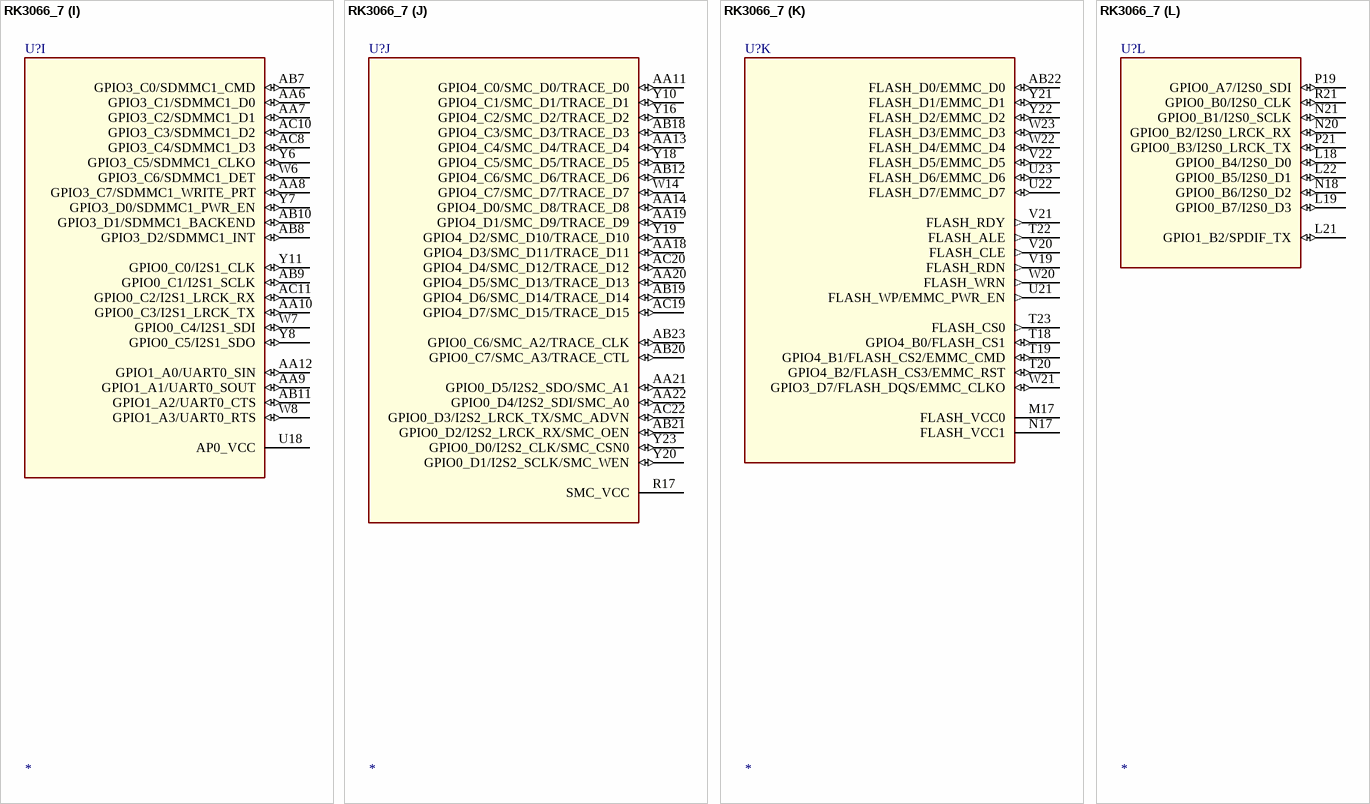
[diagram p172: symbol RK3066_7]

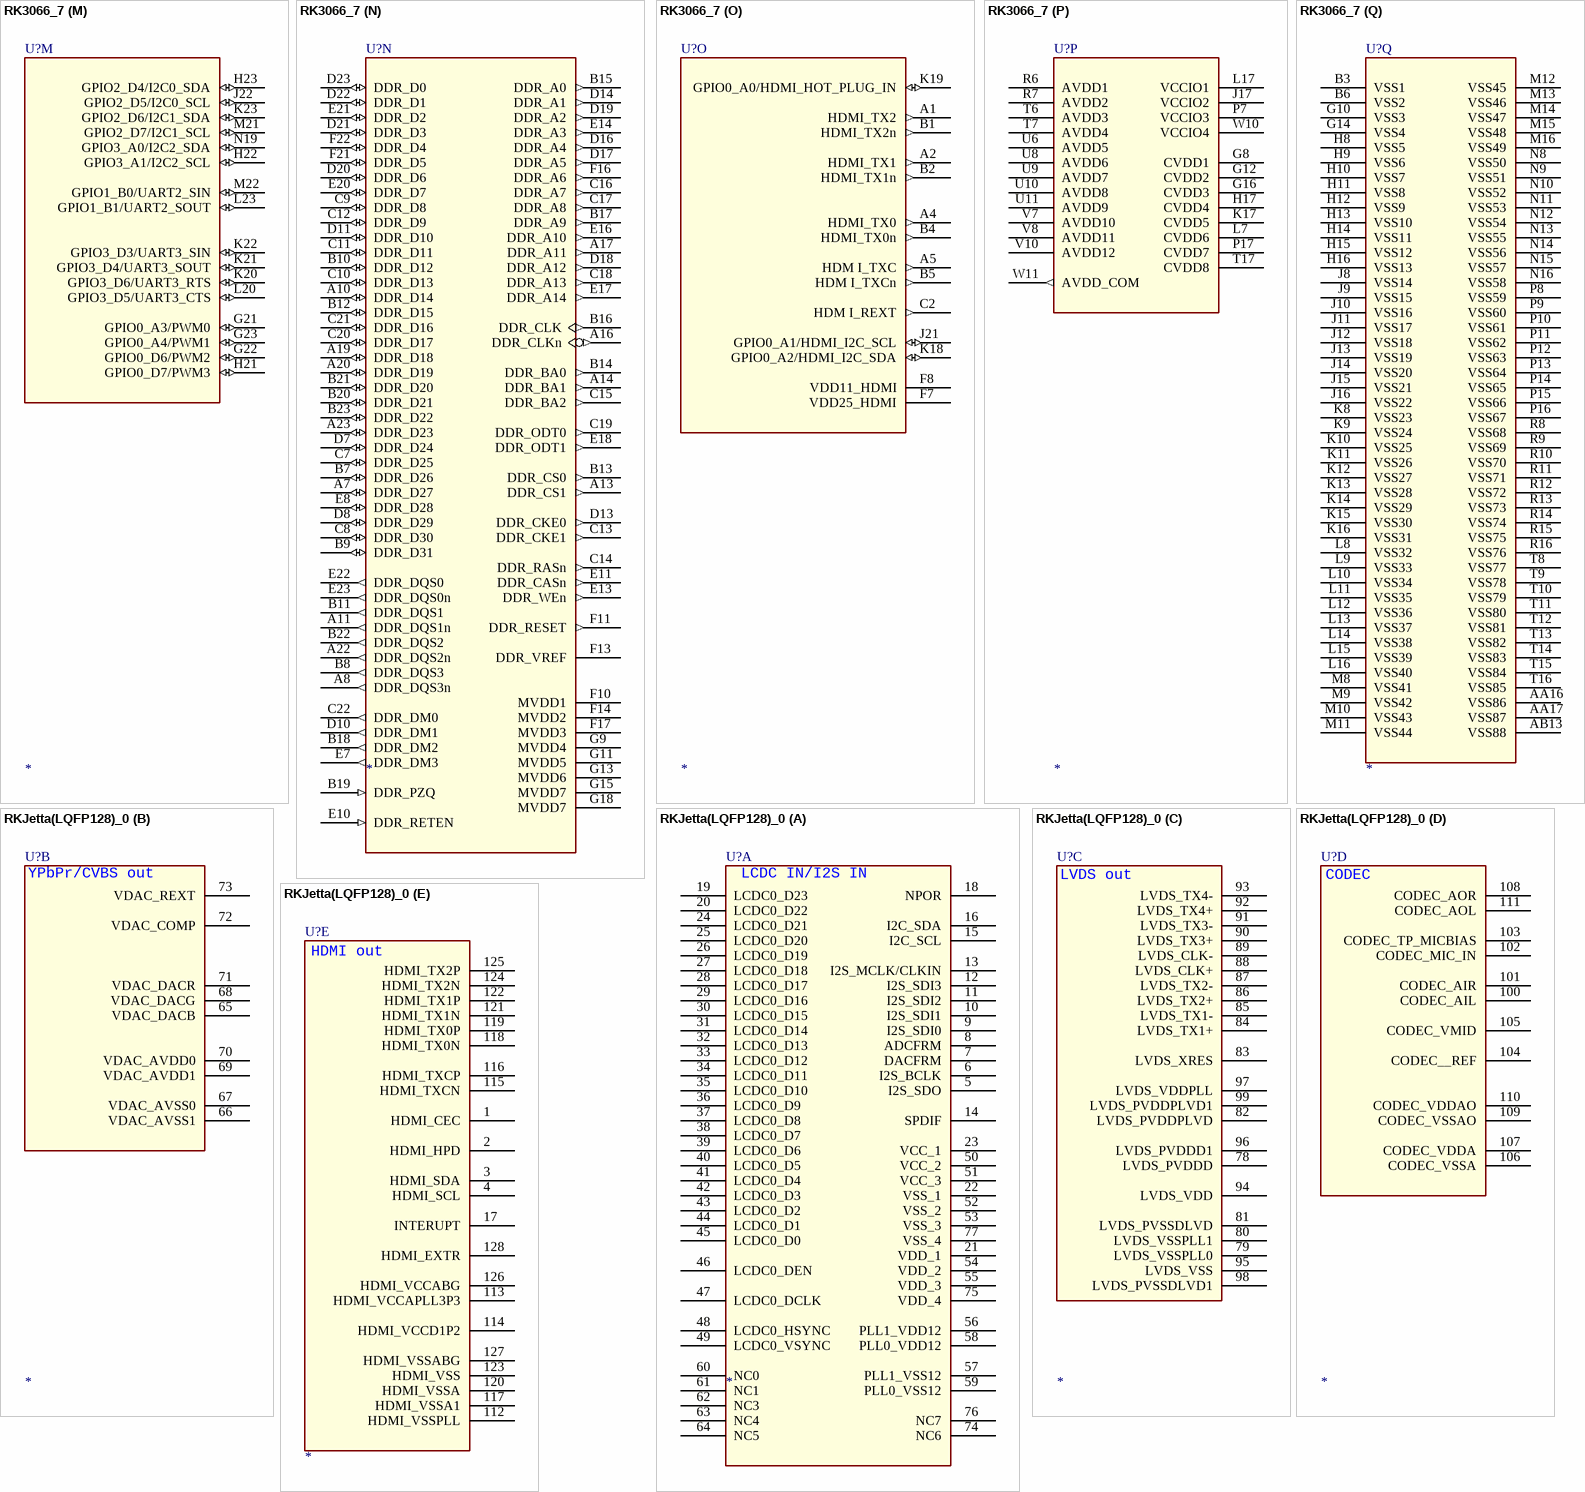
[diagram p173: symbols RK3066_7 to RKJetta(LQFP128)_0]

## RK3066_7
designator U?
footprint BGA453
part A pins: C3 LCD0_DEN (out), C4 LCD0_DCLK (out), C5 LCD0_VSYNC (out), C6 LCD0_HSYNC (out), D1 LCD0_D6 (out), D2 LCD0_D5 (out), D3 LCD0_D4 (out), D4 LCD0_D3 (out), D5 LCD0_D2 (out), D6 LCD0_D1 (out), E1 LCD0_D10 (out), E2 LCD0_D7 (out), E3 LCD0_D9 (out), E4 LCD0_D8 (out), E6 LCD0_D0 (out), F2 LCD0_D13 (out), F3 LCD0_D12 (out), F4 LCD0_D14 (out), F5 LCD0_D11 (out), G1 LCD0_D20 (out), G2 LCD0_D19 (out), G3 LCD0_D18 (out), G4 LCD0_D17 (out), G5 LCD0_D16 (out), G6 LCD0_D15 (out), H1 LCD0_D21 (out), H5 LCD0_D22 (out), H6 LCD0_D23 (out), H7 LCD0_VCC1 (power), J7 LCD0_VCC0 (power)
part B pins: H2 GPIO2_A0/LCD1_D0/SMC_A4 (io), H3 GPIO2_A1/LCD1_D1/SMC_A5 (io), H4 GPIO2_A2/LCD1_D2/SMC_A6 (io), J2 GPIO2_B7/LCD1_D14/SMC_A19/TS_D7 (io), J3 GPIO2_B6/LCD1_D14/SMC_A18/TS_SYNC (io), K1 GPIO2_C2/LCD1_D18/SMC_BIS_N1/TS_D5 (io), K2 GPIO2_C1/LCD1_D17/SMC_BIS_N0/TS_D6 (io), K3 GPIO2_B5/LCD1_D13/SMC_A17/TS_VALID (io), K4 GPIO2_C0/LCD1_D16/GPS_CLK/TS_CLKO (io), K7 LCD1_VCC (power), L1 GPIO2_C5/LCD1_D21/SPI1_RXD/TS_D2 (io), L2 GPIO2_C4/LCD1_D20/SPI1_CSN0/TS_D1 (io), L3 GPIO2_C3/LCD1_D19/SPI1_CLK/TS_D0 (io), L4 GPIO2_C7/LCD1_D23/SPI1_CSN1/TS_D4 (io), M2 GPIO2_C6/LCD1_D22/SPI1_RXD/TS_D3 (io)
part C pins: K5 CIF0_D5 (in), K6 CIF0_D2 (in), L5 CIF0_D9 (in), L6 CIF0_CLKIN (in), M3 CIF0_D8 (in), M7 CIF0_VCC (power), N1 CIF0_D4 (in), N2 CIF0_D3 (in), N3 CIF0_D7 (in), N4 GPIO1_B4/CIF0_D0 (io), N5 GPIO1_B3/CIF0_CLKO (io), N6 GPIO1_B5/CIF0_D1 (io), P1 CIF0_D6 (in), P2 CIF0_VSYNC (in), P3 CIF0_HREF (in), P4 GPIO1_B6/CIF0_D10 (io), P5 GPIO3_A3/I2C3_SCL (io), R2 GPIO3_A2/I2C3_SDA (io), R3 GPIO1_B7/CIF0_D11 (io)
part D pins: N7 CIF1_VCC (power), T1 GPIO1_C5/CIF1_D7/RMII_CRS_DVALID (io), T2 GPIO1_C0/CIF1_D2/RMII_CLKO (io), T3 GPIO1_C2/CIF1_D4/RMII_TXD1 (io), T4 GPIO1_C1/CIF1_D3/RMII_TX_EN (io), T5 GPIO1_C7/CIF1_D9/RMII_RXD0 (io), U1 GPIO1_D2/CIF1_CLKIN (io), U2 GPIO1_C4/CIF1_D6/RMII_RX_ERR (io), U3 GPIO1_C3/CIF1_D5/RMII_TXD0 (io), U4 GPIO1_D0/CIF1_VSYNC/MII_MD (io), U5 GPIO3_A5/I2C4_SCL (io), V2 GPIO1_D7/CIF1_CLKO (io), V3 GPIO1_C6/CIF1_D8/RMII_RXD1 (io), V4 GPIO1_D1/CIF1_HREF/MII_MDCLK (io), V5 GPIO3_A4/I2C4_SDA (io), W4 GPIO1_D6/CIF1_D11 (io)
part E pins: AA2 GPIO6_A4, AA3 GPIO6_A5, AA15 PVCC_3V3 (power), AB1 GPIO6_B0, AB2 GPIO6_B1, AB3 GPIO6_A1, AB4 GPIO6_A7, AB14 XOUT24M (out), AC1 GPIO6_A0, AC2 GPIO6_A3, AC4 GPIO6_A2, AC5 GPIO6_A6, AC13 DDRIO_RET_EN (out), AC14 XIN24M (in), U12 AVSS_APLL (power), U13 AVSS_DPLL (power), U14 AVSS_C/GPLL (power), V11 APLL_1V1 (power), V13 DPLL_1V1 (power), V14 C/GPLL_1V1 (power), V17 EFUSE (in), W13 PVDD_1V1 (power), Y1 CPU_PWROFF (out), Y2 CORE_PWROFF (out), Y3 DDRIO_PWROFF (out), Y4 GPIO6_B2, Y5 GPIO6_B3, Y13 CLKIN_32K (in), Y14 NPOR (in)
part F pins: AB15 HOST_RKELVIN (out), AB16 OTG_DM (io), AB17 HOST_DM (io), AC16 OTG_DP (io), AC17 HOST_DP (io), F19 GPIO0_A6/HOST_DRV (io), F20 TDO (out), G19 TDI/CPR_BYPASS (in), G20 TRSTN (in), H18 TCK/HSSCAN_SHIFT_CLOCK (in), H19 TMS/PLL_BYPASS (io), H20 RECOVER (in), P20 GPIO0_A5/OTG_DRV (io), U15 USBVDD_1V1 (power), U16 USBVDD_2V5 (power), V16 USBVDD_3V3 (power), W1 SARADC_ANI0 (in), W2 SARADC_ANI2 (in), W3 SARADC_ANI1 (in), W16 OTG_RKELVIN (out), W17 OTG_VBUS (in), Y17 OTG_ID (in)
part G pins: AA4 GPIO1_A4/UART1_RX/SPI0_CSN0 (io), AA5 GPIO4_B7/SPI0_CSN1 (io), AB5 GPIO1_A5/UART1_TX/SPI0_CLK (io), AB6 GPIO1_A6/UART1_CTSN/SPI0_RXD (io), AC7 GPIO1_A7/UART1_RTSN/SPI0_TXD (io), W18 AP1_VCC (power)
part H pins: AC23 GPIO3_B6/SDMMC0_DET (io), N22 GPIO3_B4/SDMMC0_D2 (io), N23 GPIO3_B5/SDMMC0_D3 (io), P18 GPIO3_A6/SDMMC0_RSTNO (io), P22 GPIO3_B3/SDMMC0_D1 (io), P23 GPIO3_B7/SDMMC0_WRITE_PRT (io), R22 GPIO3_A7/SDMMC0_PWR_EN (io), T21 GPIO3_B0/SDMMC0_CLKOUT (io), U19 GPIO3_B2/SDMMC0_D0 (io), U20 GPIO3_B1/SDMMC0_CMD (io)
part I pins: AA6 GPIO3_C1/SDMMC1_D0 (io), AA7 GPIO3_C2/SDMMC1_D1 (io), AA8 GPIO3_C7/SDMMC1_WRITE_PRT (io), AA9 GPIO1_A1/UART0_SOUT (io), AA10 GPIO0_C3/I2S1_LRCK_TX (io), AA12 GPIO1_A0/UART0_SIN (io), AB7 GPIO3_C0/SDMMC1_CMD (io), AB8 GPIO3_D2/SDMMC1_INT (io), AB9 GPIO0_C1/I2S1_SCLK (io), AB10 GPIO3_D1/SDMMC1_BACKEND (io), AB11 GPIO1_A2/UART0_CTS (io), AC8 GPIO3_C4/SDMMC1_D3 (io), AC10 GPIO3_C3/SDMMC1_D2 (io), AC11 GPIO0_C2/I2S1_LRCK_RX (io), U18 AP0_VCC (power), W6 GPIO3_C6/SDMMC1_DET (io), W7 GPIO0_C4/I2S1_SDI (io), W8 GPIO1_A3/UART0_RTS (io), Y6 GPIO3_C5/SDMMC1_CLKO (io), Y7 GPIO3_D0/SDMMC1_PWR_EN (io), Y8 GPIO0_C5/I2S1_SDO (io), Y11 GPIO0_C0/I2S1_CLK (io)
part J pins: AA11 GPIO4_C0/SMC_D0/TRACE_D0 (io), AA13 GPIO4_C4/SMC_D4/TRACE_D4 (io), AA14 GPIO4_D0/SMC_D8/TRACE_D8 (io), AA18 GPIO4_D3/SMC_D11/TRACE_D11 (io), AA19 GPIO4_D1/SMC_D9/TRACE_D9 (io), AA20 GPIO4_D5/SMC_D13/TRACE_D13 (io), AA21 GPIO0_D5/I2S2_SDO/SMC_A1 (io), AA22 GPIO0_D4/I2S2_SDI/SMC_A0 (io), AB12 GPIO4_C6/SMC_D6/TRACE_D6 (io), AB18 GPIO4_C3/SMC_D3/TRACE_D3 (io), AB19 GPIO4_D6/SMC_D14/TRACE_D14 (io), AB20 GPIO0_C7/SMC_A3/TRACE_CTL (io), AB21 GPIO0_D2/I2S2_LRCK_RX/SMC_OEN (io), AB23 GPIO0_C6/SMC_A2/TRACE_CLK (io), AC19 GPIO4_D7/SMC_D15/TRACE_D15 (io), AC20 GPIO4_D4/SMC_D12/TRACE_D12 (io), AC22 GPIO0_D3/I2S2_LRCK_TX/SMC_ADVN (io), R17 SMC_VCC (power), W14 GPIO4_C7/SMC_D7/TRACE_D7 (io), Y10 GPIO4_C1/SMC_D1/TRACE_D1 (io), Y16 GPIO4_C2/SMC_D2/TRACE_D2 (io), Y18 GPIO4_C5/SMC_D5/TRACE_D5 (io), Y19 GPIO4_D2/SMC_D10/TRACE_D10 (io), Y20 GPIO0_D1/I2S2_SCLK/SMC_WEN (io), Y23 GPIO0_D0/I2S2_CLK/SMC_CSN0 (io)
part K pins: AB22 FLASH_D0/EMMC_D0 (io), M17 FLASH_VCC0 (power), N17 FLASH_VCC1 (power), T18 GPIO4_B0/FLASH_CS1 (io), T19 GPIO4_B1/FLASH_CS2/EMMC_CMD (io), T20 GPIO4_B2/FLASH_CS3/EMMC_RST (io), T22 FLASH_ALE (out), T23 FLASH_CS0 (out), U21 FLASH_WP/EMMC_PWR_EN (out), U22 FLASH_D7/EMMC_D7 (io), U23 FLASH_D6/EMMC_D6 (io), V19 FLASH_RDN (out), V20 FLASH_CLE (out), V21 FLASH_RDY (out), V22 FLASH_D5/EMMC_D5 (io), W20 FLASH_WRN (out), W21 GPIO3_D7/FLASH_DQS/EMMC_CLKO (io), W22 FLASH_D4/EMMC_D4 (io), W23 FLASH_D3/EMMC_D3 (io), Y21 FLASH_D1/EMMC_D1 (io), Y22 FLASH_D2/EMMC_D2 (io)
part L pins: L18 GPIO0_B4/I2S0_D0 (io), L19 GPIO0_B7/I2S0_D3 (io), L21 GPIO1_B2/SPDIF_TX (io), L22 GPIO0_B5/I2S0_D1 (io), N18 GPIO0_B6/I2S0_D2 (io), N20 GPIO0_B2/I2S0_LRCK_RX (io), N21 GPIO0_B1/I2S0_SCLK (io), P19 GPIO0_A7/I2S0_SDI (io), P21 GPIO0_B3/I2S0_LRCK_TX (io), R21 GPIO0_B0/I2S0_CLK (io)
part M pins: G21 GPIO0_A3/PWM0 (io), G22 GPIO0_D6/PWM2 (io), G23 GPIO0_A4/PWM1 (io), H21 GPIO0_D7/PWM3 (io), H22 GPIO3_A1/I2C2_SCL (io), H23 GPIO2_D4/I2C0_SDA (io), J22 GPIO2_D5/I2C0_SCL (io), K20 GPIO3_D6/UART3_RTS (io), K21 GPIO3_D4/UART3_SOUT (io), K22 GPIO3_D3/UART3_SIN (io), K23 GPIO2_D6/I2C1_SDA (io), L20 GPIO3_D5/UART3_CTS (io), L23 GPIO1_B1/UART2_SOUT (io), M21 GPIO2_D7/I2C1_SCL (io), M22 GPIO1_B0/UART2_SIN (io), N19 GPIO3_A0/I2C2_SDA (io)
part N pins: A7 DDR_D27 (io), A8 DDR_DQS3n (out), A10 DDR_D14 (io), A11 DDR_DQS1n (out), A13 DDR_CS1 (out), A14 DDR_BA1 (out), A16 DDR_CLKn (out), A17 DDR_A11 (out), A19 DDR_D18 (io), A20 DDR_D19 (io), A22 DDR_DQS2n (out), A23 DDR_D23 (io), B7 DDR_D26 (io), B8 DDR_DQS3 (out), B9 DDR_D31 (io), B10 DDR_D12 (io), B11 DDR_DQS1 (out), B12 DDR_D15 (io), B13 DDR_CS0 (out), B14 DDR_BA0 (out), B15 DDR_A0 (out), B16 DDR_CLK (out), B17 DDR_A9 (out), B18 DDR_DM2 (out), B19 DDR_PZQ (in), B20 DDR_D21 (io), B21 DDR_D20 (io), B22 DDR_DQS2 (out), B23 DDR_D22 (io), C7 DDR_D25 (io), C8 DDR_D30 (io), C9 DDR_D8 (io), C10 DDR_D13 (io), C11 DDR_D11 (io), C12 DDR_D9 (io), C13 DDR_CKE1 (out), C14 DDR_RASn (out), C15 DDR_BA2 (out), C16 DDR_A7 (out), C17 DDR_A8 (out), C18 DDR_A13 (out), C19 DDR_ODT0 (out), C20 DDR_D17 (io), C21 DDR_D16 (io), C22 DDR_DM0 (out), D7 DDR_D24 (io), D8 DDR_D29 (io), D10 DDR_DM1 (out), D11 DDR_D10 (io), D13 DDR_CKE0 (out), D14 DDR_A1 (out), D16 DDR_A4 (out), D17 DDR_A5 (out), D18 DDR_A12 (out), D19 DDR_A2 (out), D20 DDR_D6 (io), D21 DDR_D3 (io), D22 DDR_D1 (io), D23 DDR_D0 (io), E7 DDR_DM3 (out), E8 DDR_D28 (io), E10 DDR_RETEN (in), E11 DDR_CASn (out), E13 DDR_WEn (out), E14 DDR_A3 (out), E16 DDR_A10 (out), E17 DDR_A14 (out), E18 DDR_ODT1 (out), E20 DDR_D7 (io), E21 DDR_D2 (io), E22 DDR_DQS0 (out), E23 DDR_DQS0n (out), F10 MVDD1 (power), F11 DDR_RESET (out), F13 DDR_VREF (power), F14 MVDD2 (power), F16 DDR_A6 (out), F17 MVDD3 (power), F21 DDR_D5 (io), F22 DDR_D4 (io), G9 MVDD4 (power), G11 MVDD5 (power), G13 MVDD6 (power), G15 MVDD7 (power), G18 MVDD7 (power)
part O pins: A1 HDMI_TX2 (out), A2 HDMI_TX1 (out), A4 HDMI_TX0 (out), A5 HDM I_TXC (out), B1 HDMI_TX2n (out), B2 HDMI_TX1n (out), B4 HDMI_TX0n (out), B5 HDM I_TXCn (out), C2 HDM I_REXT (out), F7 VDD25_HDMI (power), F8 VDD11_HDMI (power), J21 GPIO0_A1/HDMI_I2C_SCL (io), K18 GPIO0_A2/HDMI_I2C_SDA (io), K19 GPIO0_A0/HDMI_HOT_PLUG_IN (io)
part P pins: G8 CVDD1 (power), G12 CVDD2 (power), G16 CVDD3 (power), H17 CVDD4 (power), J17 VCCIO2 (power), K17 CVDD5 (power), L7 CVDD6 (power), L17 VCCIO1 (power), P7 VCCIO3 (power), P17 CVDD7 (power), R6 AVDD1 (power), R7 AVDD2 (power), T6 AVDD3 (power), T7 AVDD4 (power), T17 CVDD8 (power), U6 AVDD5 (power), U8 AVDD6 (power), U9 AVDD7 (power), U10 AVDD8 (power), U11 AVDD9 (power), V7 AVDD10 (power), V8 AVDD11 (power), V10 AVDD12 (power), W10 VCCIO4 (power), W11 AVDD_COM (out)
part Q pins: AA16 VSS86 (power), AA17 VSS87 (power), AB13 VSS88 (power), B3 VSS1 (power), B6 VSS2 (power), G10 VSS3 (power), G14 VSS4 (power), H8 VSS5 (power), H9 VSS6 (power), H10 VSS7 (power), H11 VSS8 (power), H12 VSS9 (power), H13 VSS10 (power), H14 VSS11 (power), H15 VSS12 (power), H16 VSS13 (power), J8 VSS14 (power), J9 VSS15 (power), J10 VSS16 (power), J11 VSS17 (power), J12 VSS18 (power), J13 VSS19 (power), J14 VSS20 (power), J15 VSS21 (power), J16 VSS22 (power), K8 VSS23 (power), K9 VSS24 (power), K10 VSS25 (power), K11 VSS26 (power), K12 VSS27 (power), K13 VSS28 (power), K14 VSS29 (power), K15 VSS30 (power), K16 VSS31 (power), L8 VSS32 (power), L9 VSS33 (power), L10 VSS34 (power), L11 VSS35 (power), L12 VSS36 (power), L13 VSS37 (power), L14 VSS38 (power), L15 VSS39 (power), L16 VSS40 (power), M8 VSS41 (power), M9 VSS42 (power), M10 VSS43 (power), M11 VSS44 (power), M12 VSS45 (power), M13 VSS46 (power), M14 VSS47 (power), M15 VSS48 (power), M16 VSS49 (power), N8 VSS50 (power), N9 VSS51 (power), N10 VSS52 (power), N11 VSS53 (power), N12 VSS54 (power), N13 VSS55 (power), N14 VSS56 (power), N15 VSS57 (power), N16 VSS58 (power), P8 VSS59 (power), P9 VSS60 (power), P10 VSS61 (power), P11 VSS62 (power), P12 VSS63 (power), P13 VSS64 (power), P14 VSS65 (power), P15 VSS66 (power), P16 VSS67 (power), R8 VSS68 (power), R9 VSS69 (power), R10 VSS70 (power), R11 VSS71 (power), R12 VSS72 (power), R13 VSS73 (power), R14 VSS74 (power), R15 VSS75 (power), R16 VSS76 (power), T8 VSS77 (power), T9 VSS78 (power), T10 VSS79 (power), T11 VSS80 (power), T12 VSS81 (power), T13 VSS82 (power), T14 VSS83 (power), T15 VSS84 (power), T16 VSS85 (power)

## RKJetta(LQFP128)_0
designator U?
footprint LQFP128
part A pins: 5 I2S_SDO, 6 I2S_BCLK, 7 DACFRM, 8 ADCFRM, 9 I2S_SDI0, 10 I2S_SDI1, 11 I2S_SDI2, 12 I2S_SDI3, 13 I2S_MCLK/CLKIN, 14 SPDIF, 15 I2C_SCL, 16 I2C_SDA, 18 NPOR, 19 LCDC0_D23, 20 LCDC0_D22, 21 VDD_1, 22 VSS_1, 23 VCC_1, 24 LCDC0_D21, 25 LCDC0_D20, 26 LCDC0_D19, 27 LCDC0_D18, 28 LCDC0_D17, 29 LCDC0_D16, 30 LCDC0_D15, 31 LCDC0_D14, 32 LCDC0_D13, 33 LCDC0_D12, 34 LCDC0_D11, 35 LCDC0_D10, 36 LCDC0_D9, 37 LCDC0_D8, 38 LCDC0_D7, 39 LCDC0_D6, 40 LCDC0_D5, 41 LCDC0_D4, 42 LCDC0_D3, 43 LCDC0_D2, 44 LCDC0_D1, 45 LCDC0_D0, 46 LCDC0_DEN, 47 LCDC0_DCLK, 48 LCDC0_HSYNC, 49 LCDC0_VSYNC, 50 VCC_2, 51 VCC_3, 52 VSS_2, 53 VSS_3, 54 VDD_2, 55 VDD_3, 56 PLL1_VDD12, 57 PLL1_VSS12, 58 PLL0_VDD12, 59 PLL0_VSS12, 60 NC0, 61 NC1, 62 NC3, 63 NC4, 64 NC5, 74 NC6, 75 VDD_4, 76 NC7, 77 VSS_4
part B pins: 65 VDAC_DACB, 66 VDAC_AVSS1, 67 VDAC_AVSS0, 68 VDAC_DACG, 69 VDAC_AVDD1, 70 VDAC_AVDD0, 71 VDAC_DACR, 72 VDAC_COMP, 73 VDAC_REXT
part C pins: 78 LVDS_PVDDD, 79 LVDS_VSSPLL0, 80 LVDS_VSSPLL1, 81 LVDS_PVSSDLVD, 82 LVDS_PVDDPLVD, 83 LVDS_XRES, 84 LVDS_TX1+, 85 LVDS_TX1-, 86 LVDS_TX2+, 87 LVDS_TX2-, 88 LVDS_CLK+, 89 LVDS_CLK-, 90 LVDS_TX3+, 91 LVDS_TX3-, 92 LVDS_TX4+, 93 LVDS_TX4-, 94 LVDS_VDD, 95 LVDS_VSS, 96 LVDS_PVDDD1, 97 LVDS_VDDPLL, 98 LVDS_PVSSDLVD1, 99 LVDS_PVDDPLVD1
part D pins: 100 CODEC_AIL, 101 CODEC_AIR, 102 CODEC_MIC_IN, 103 CODEC_TP_MICBIAS, 104 CODEC__REF, 105 CODEC_VMID, 106 CODEC_VSSA, 107 CODEC_VDDA, 108 CODEC_AOR, 109 CODEC_VSSAO, 110 CODEC_VDDAO, 111 CODEC_AOL
part E pins: 1 HDMI_CEC, 2 HDMI_HPD, 3 HDMI_SDA, 4 HDMI_SCL, 17 INTERUPT, 112 HDMI_VSSPLL, 113 HDMI_VCCAPLL3P3, 114 HDMI_VCCD1P2, 115 HDMI_TXCN, 116 HDMI_TXCP, 117 HDMI_VSSA1, 118 HDMI_TX0N, 119 HDMI_TX0P, 120 HDMI_VSSA, 121 HDMI_TX1N, 122 HDMI_TX1P, 123 HDMI_VSS, 124 HDMI_TX2N, 125 HDMI_TX2P, 126 HDMI_VCCABG, 127 HDMI_VSSABG, 128 HDMI_EXTR

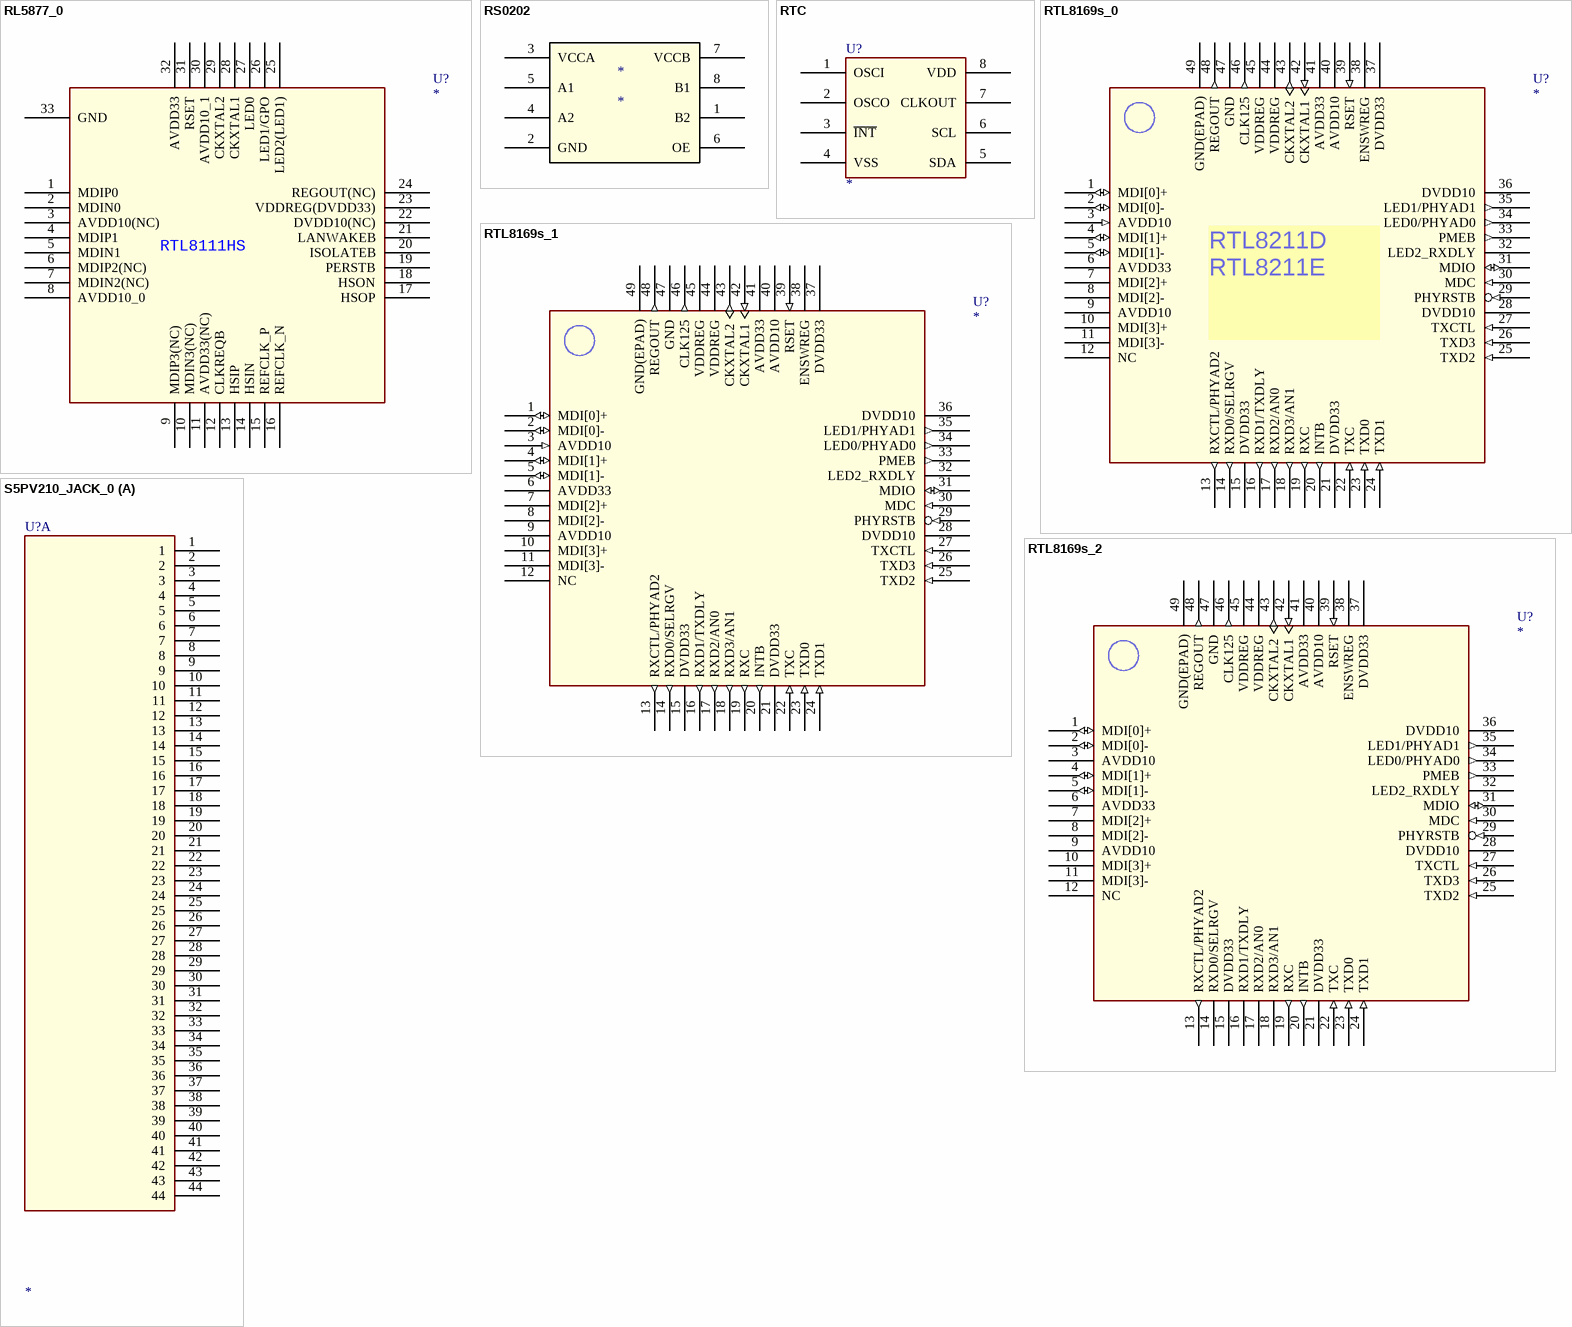
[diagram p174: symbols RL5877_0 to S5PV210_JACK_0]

## RL5877_0
designator U?
pins: 1 MDIP0, 2 MDIN0, 3 AVDD10(NC), 4 MDIP1, 5 MDIN1, 6 MDIP2(NC), 7 MDIN2(NC), 8 AVDD10_0, 9 MDIP3(NC), 10 MDIN3(NC), 11 AVDD33(NC), 12 CLKREQB, 13 HSIP (power), 14 HSIN (power), 15 REFCLK_P, 16 REFCLK_N, 17 HSOP, 18 HSON, 19 PERSTB, 20 ISOLATEB, 21 LANWAKEB, 22 DVDD10(NC) (hiz), 23 VDDREG(DVDD33), 24 REGOUT(NC), 25 LED2(LED1), 26 LED1/GPO (hiz), 27 LED0, 28 CKXTAL1, 29 CKXTAL2, 30 AVDD10_1, 31 RSET, 32 AVDD33, 33 GND

## RS0202
designator *
pins: 1 B2, 2 GND, 3 VCCA, 4 A2, 5 A1, 6 OE, 7 VCCB, 8 B1

## RTC
designator U?
pins: 1 OSCI, 2 OSCO, 3 ~{INT}, 4 VSS, 5 SDA, 6 SCL, 7 CLKOUT, 8 VDD

## RTL8169s_0
designator U?
pins: 1 MDI[0]+ (io), 2 MDI[0]- (io), 3 AVDD10 (in), 4 MDI[1]+ (io), 5 MDI[1]- (io), 6 AVDD33 (power), 7 MDI[2]+, 8 MDI[2]-, 9 AVDD10 (power), 10 MDI[3]+, 11 MDI[3]-, 12 NC, 13 RXCTL/PHYAD2 (out), 14 RXD0/SELRGV (out), 15 DVDD33 (power), 16 RXD1/TXDLY (out), 17 RXD2/AN0 (out), 18 RXD3/AN1 (out), 19 RXC (out), 20 INTB (out), 21 DVDD33 (power), 22 TXC (in), 23 TXD0 (in), 24 TXD1 (in), 25 TXD2 (in), 26 TXD3 (in), 27 TXCTL (in), 28 DVDD10 (power), 29 PHYRSTB (in), 30 MDC (in), 31 MDIO (io), 32 LED2_RXDLY, 33 PMEB (out), 34 LED0/PHYAD0 (out), 35 LED1/PHYAD1 (out), 36 DVDD10 (power), 37 DVDD33 (power), 38 ENSWREG, 39 RSET (in), 40 AVDD10 (power), 41 AVDD33 (power), 42 CKXTAL1 (in), 43 CKXTAL2 (out), 44 VDDREG (power), 45 VDDREG (power), 46 CLK125 (out), 47 GND, 48 REGOUT (out), 49 GND(EPAD)

## RTL8169s_1
designator U?
pins: 1 MDI[0]+ (io), 2 MDI[0]- (io), 3 AVDD10 (in), 4 MDI[1]+ (io), 5 MDI[1]- (io), 6 AVDD33 (power), 7 MDI[2]+, 8 MDI[2]-, 9 AVDD10 (power), 10 MDI[3]+, 11 MDI[3]-, 12 NC, 13 RXCTL/PHYAD2 (out), 14 RXD0/SELRGV (out), 15 DVDD33 (power), 16 RXD1/TXDLY (out), 17 RXD2/AN0 (out), 18 RXD3/AN1 (out), 19 RXC (out), 20 INTB (out), 21 DVDD33 (power), 22 TXC (in), 23 TXD0 (in), 24 TXD1 (in), 25 TXD2 (in), 26 TXD3 (in), 27 TXCTL (in), 28 DVDD10 (power), 29 PHYRSTB (in), 30 MDC (in), 31 MDIO (io), 32 LED2_RXDLY, 33 PMEB (out), 34 LED0/PHYAD0 (out), 35 LED1/PHYAD1 (out), 36 DVDD10 (power), 37 DVDD33 (power), 38 ENSWREG, 39 RSET (in), 40 AVDD10 (power), 41 AVDD33 (power), 42 CKXTAL1 (in), 43 CKXTAL2 (out), 44 VDDREG (power), 45 VDDREG (power), 46 CLK125 (out), 47 GND, 48 REGOUT (out), 49 GND(EPAD)

## RTL8169s_2
designator U?
pins: 1 MDI[0]+ (io), 2 MDI[0]- (io), 3 AVDD10 (power), 4 MDI[1]+ (io), 5 MDI[1]- (io), 6 AVDD33 (power), 7 MDI[2]+, 8 MDI[2]-, 9 AVDD10 (power), 10 MDI[3]+, 11 MDI[3]-, 12 NC, 13 RXCTL/PHYAD2 (out), 14 RXD0/SELRGV, 15 DVDD33 (power), 16 RXD1/TXDLY, 17 RXD2/AN0, 18 RXD3/AN1, 19 RXC (out), 20 INTB (out), 21 DVDD33 (power), 22 TXC (in), 23 TXD0 (in), 24 TXD1 (in), 25 TXD2 (in), 26 TXD3 (in), 27 TXCTL (in), 28 DVDD10 (power), 29 PHYRSTB (in), 30 MDC (in), 31 MDIO (io), 32 LED2_RXDLY, 33 PMEB (out), 34 LED0/PHYAD0 (out), 35 LED1/PHYAD1 (out), 36 DVDD10 (power), 37 DVDD33 (power), 38 ENSWREG, 39 RSET (in), 40 AVDD10 (power), 41 AVDD33 (power), 42 CKXTAL1 (in), 43 CKXTAL2 (out), 44 VDDREG (power), 45 VDDREG (power), 46 CLK125 (out), 47 GND, 48 REGOUT (out), 49 GND(EPAD)

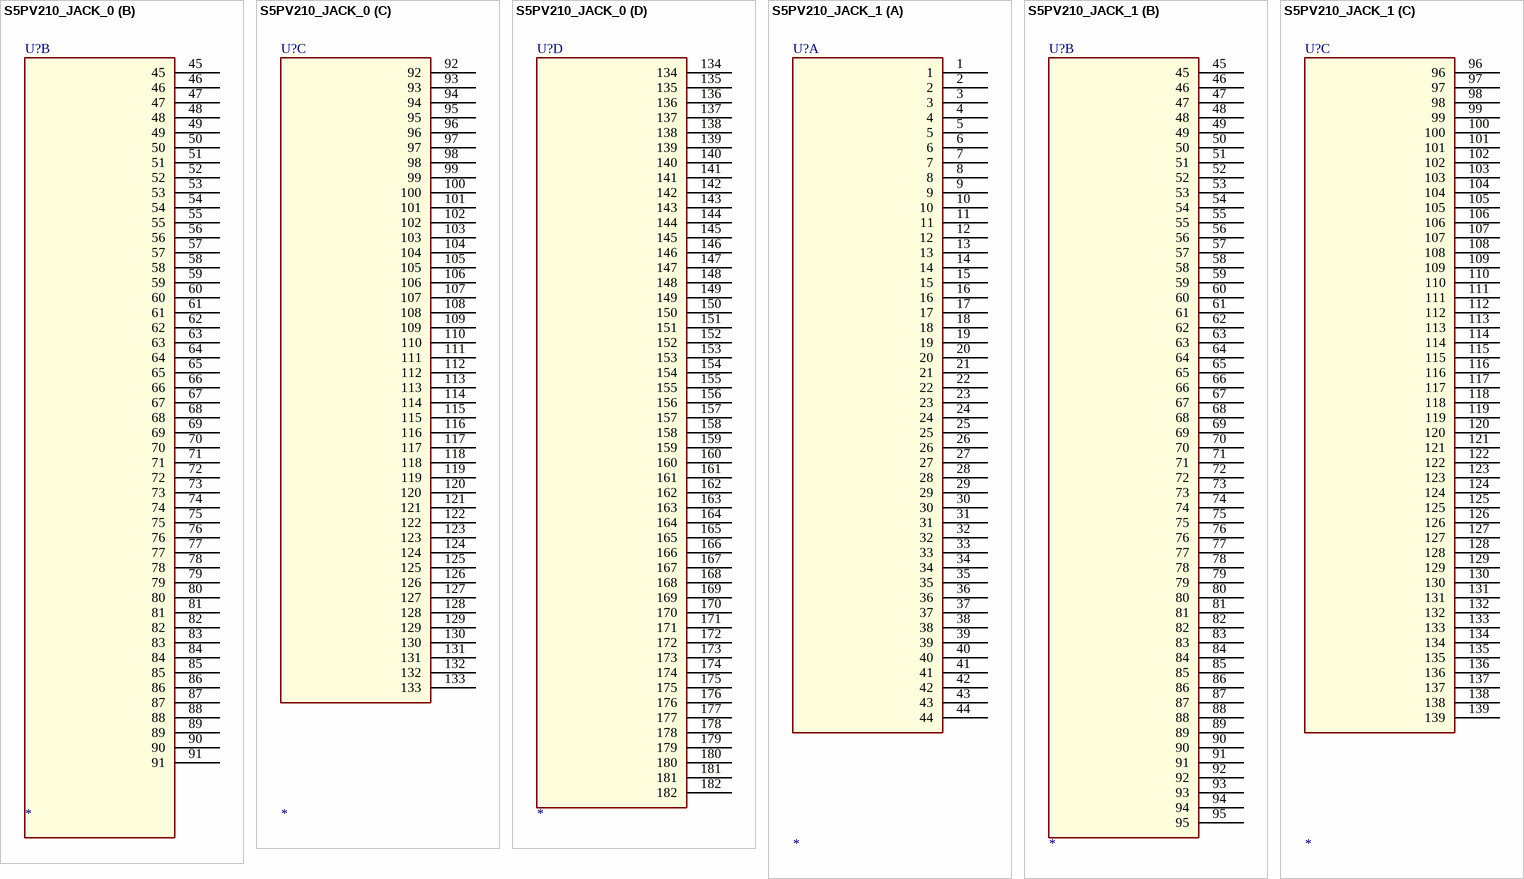
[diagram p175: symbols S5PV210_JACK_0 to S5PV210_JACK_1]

## S5PV210_JACK_0
designator U?
footprint S5PV210_JACK
part A pins: 1, 2, 3, 4, 5, 6, 7, 8, 9, 10, 11, 12, 13, 14, 15, 16, 17, 18, 19, 20, 21, 22, 23, 24, 25, 26, 27, 28, 29, 30, 31, 32, 33, 34, 35, 36, 37, 38, 39, 40, 41, 42, 43, 44
part B pins: 45, 46, 47, 48, 49, 50, 51, 52, 53, 54, 55, 56, 57, 58, 59, 60, 61, 62, 63, 64, 65, 66, 67, 68, 69, 70, 71, 72, 73, 74, 75, 76, 77, 78, 79, 80, 81, 82, 83, 84, 85, 86, 87, 88, 89, 90, 91
part C pins: 92, 93, 94, 95, 96, 97, 98, 99, 100, 101, 102, 103, 104, 105, 106, 107, 108, 109, 110, 111, 112, 113, 114, 115, 116, 117, 118, 119, 120, 121, 122, 123, 124, 125, 126, 127, 128, 129, 130, 131, 132, 133
part D pins: 134, 135, 136, 137, 138, 139, 140, 141, 142, 143, 144, 145, 146, 147, 148, 149, 150, 151, 152, 153, 154, 155, 156, 157, 158, 159, 160, 161, 162, 163, 164, 165, 166, 167, 168, 169, 170, 171, 172, 173, 174, 175, 176, 177, 178, 179, 180, 181, 182

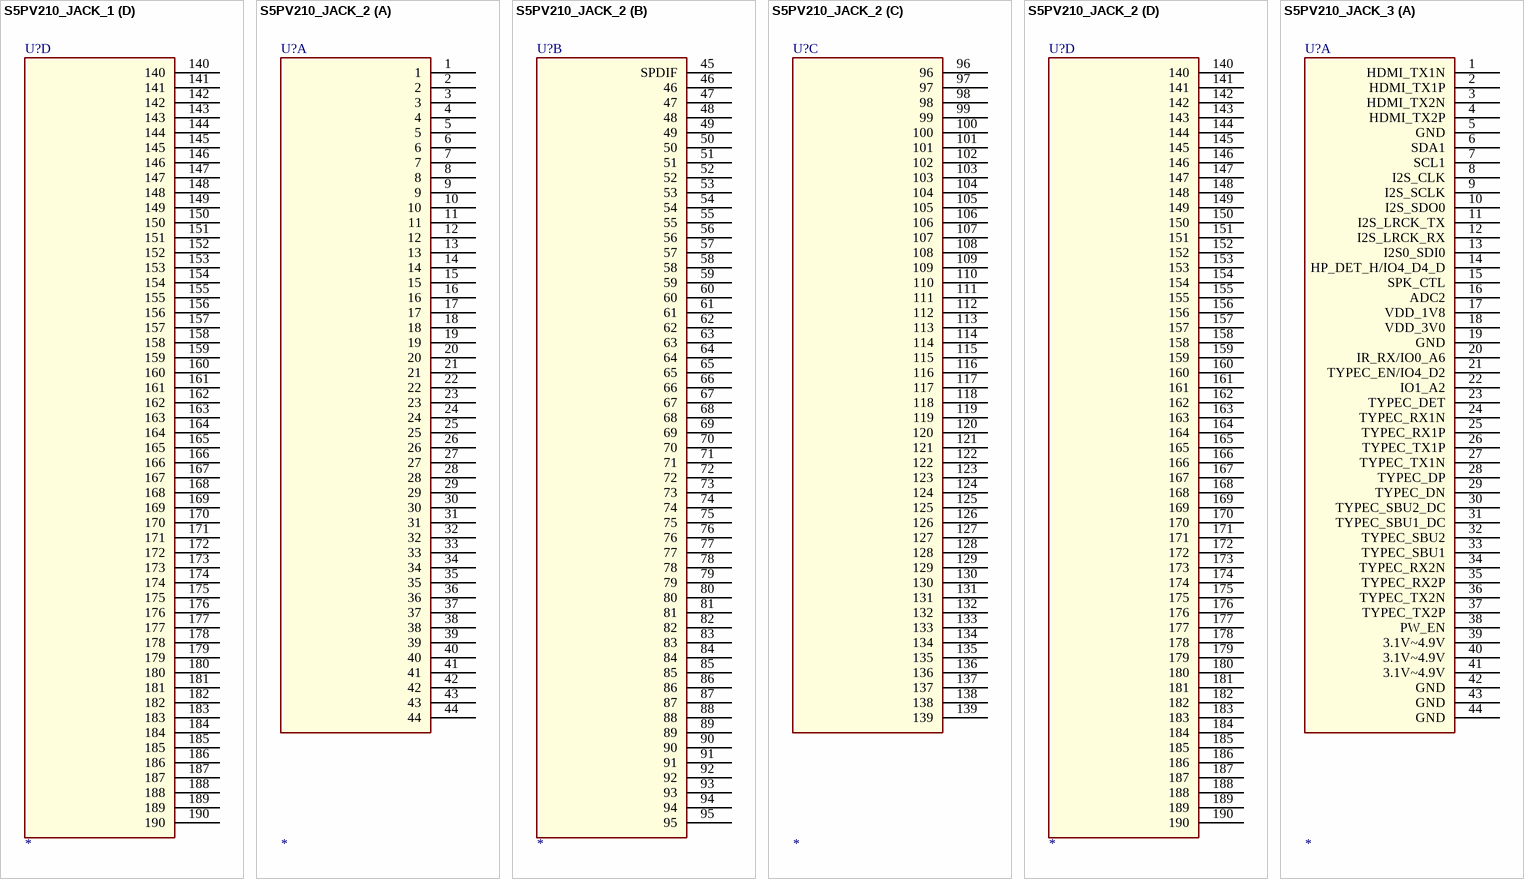
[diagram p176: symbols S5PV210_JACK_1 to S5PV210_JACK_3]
